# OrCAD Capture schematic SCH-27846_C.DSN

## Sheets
1 TITLE PAGE: title: TWR- KW21D256; rev: C; company: Freescale Semiconductor; note: SCH-27694 PDF: SPF-27694; note: 6501 William Cannon Drive West; note: Austin, TX 78735-8598
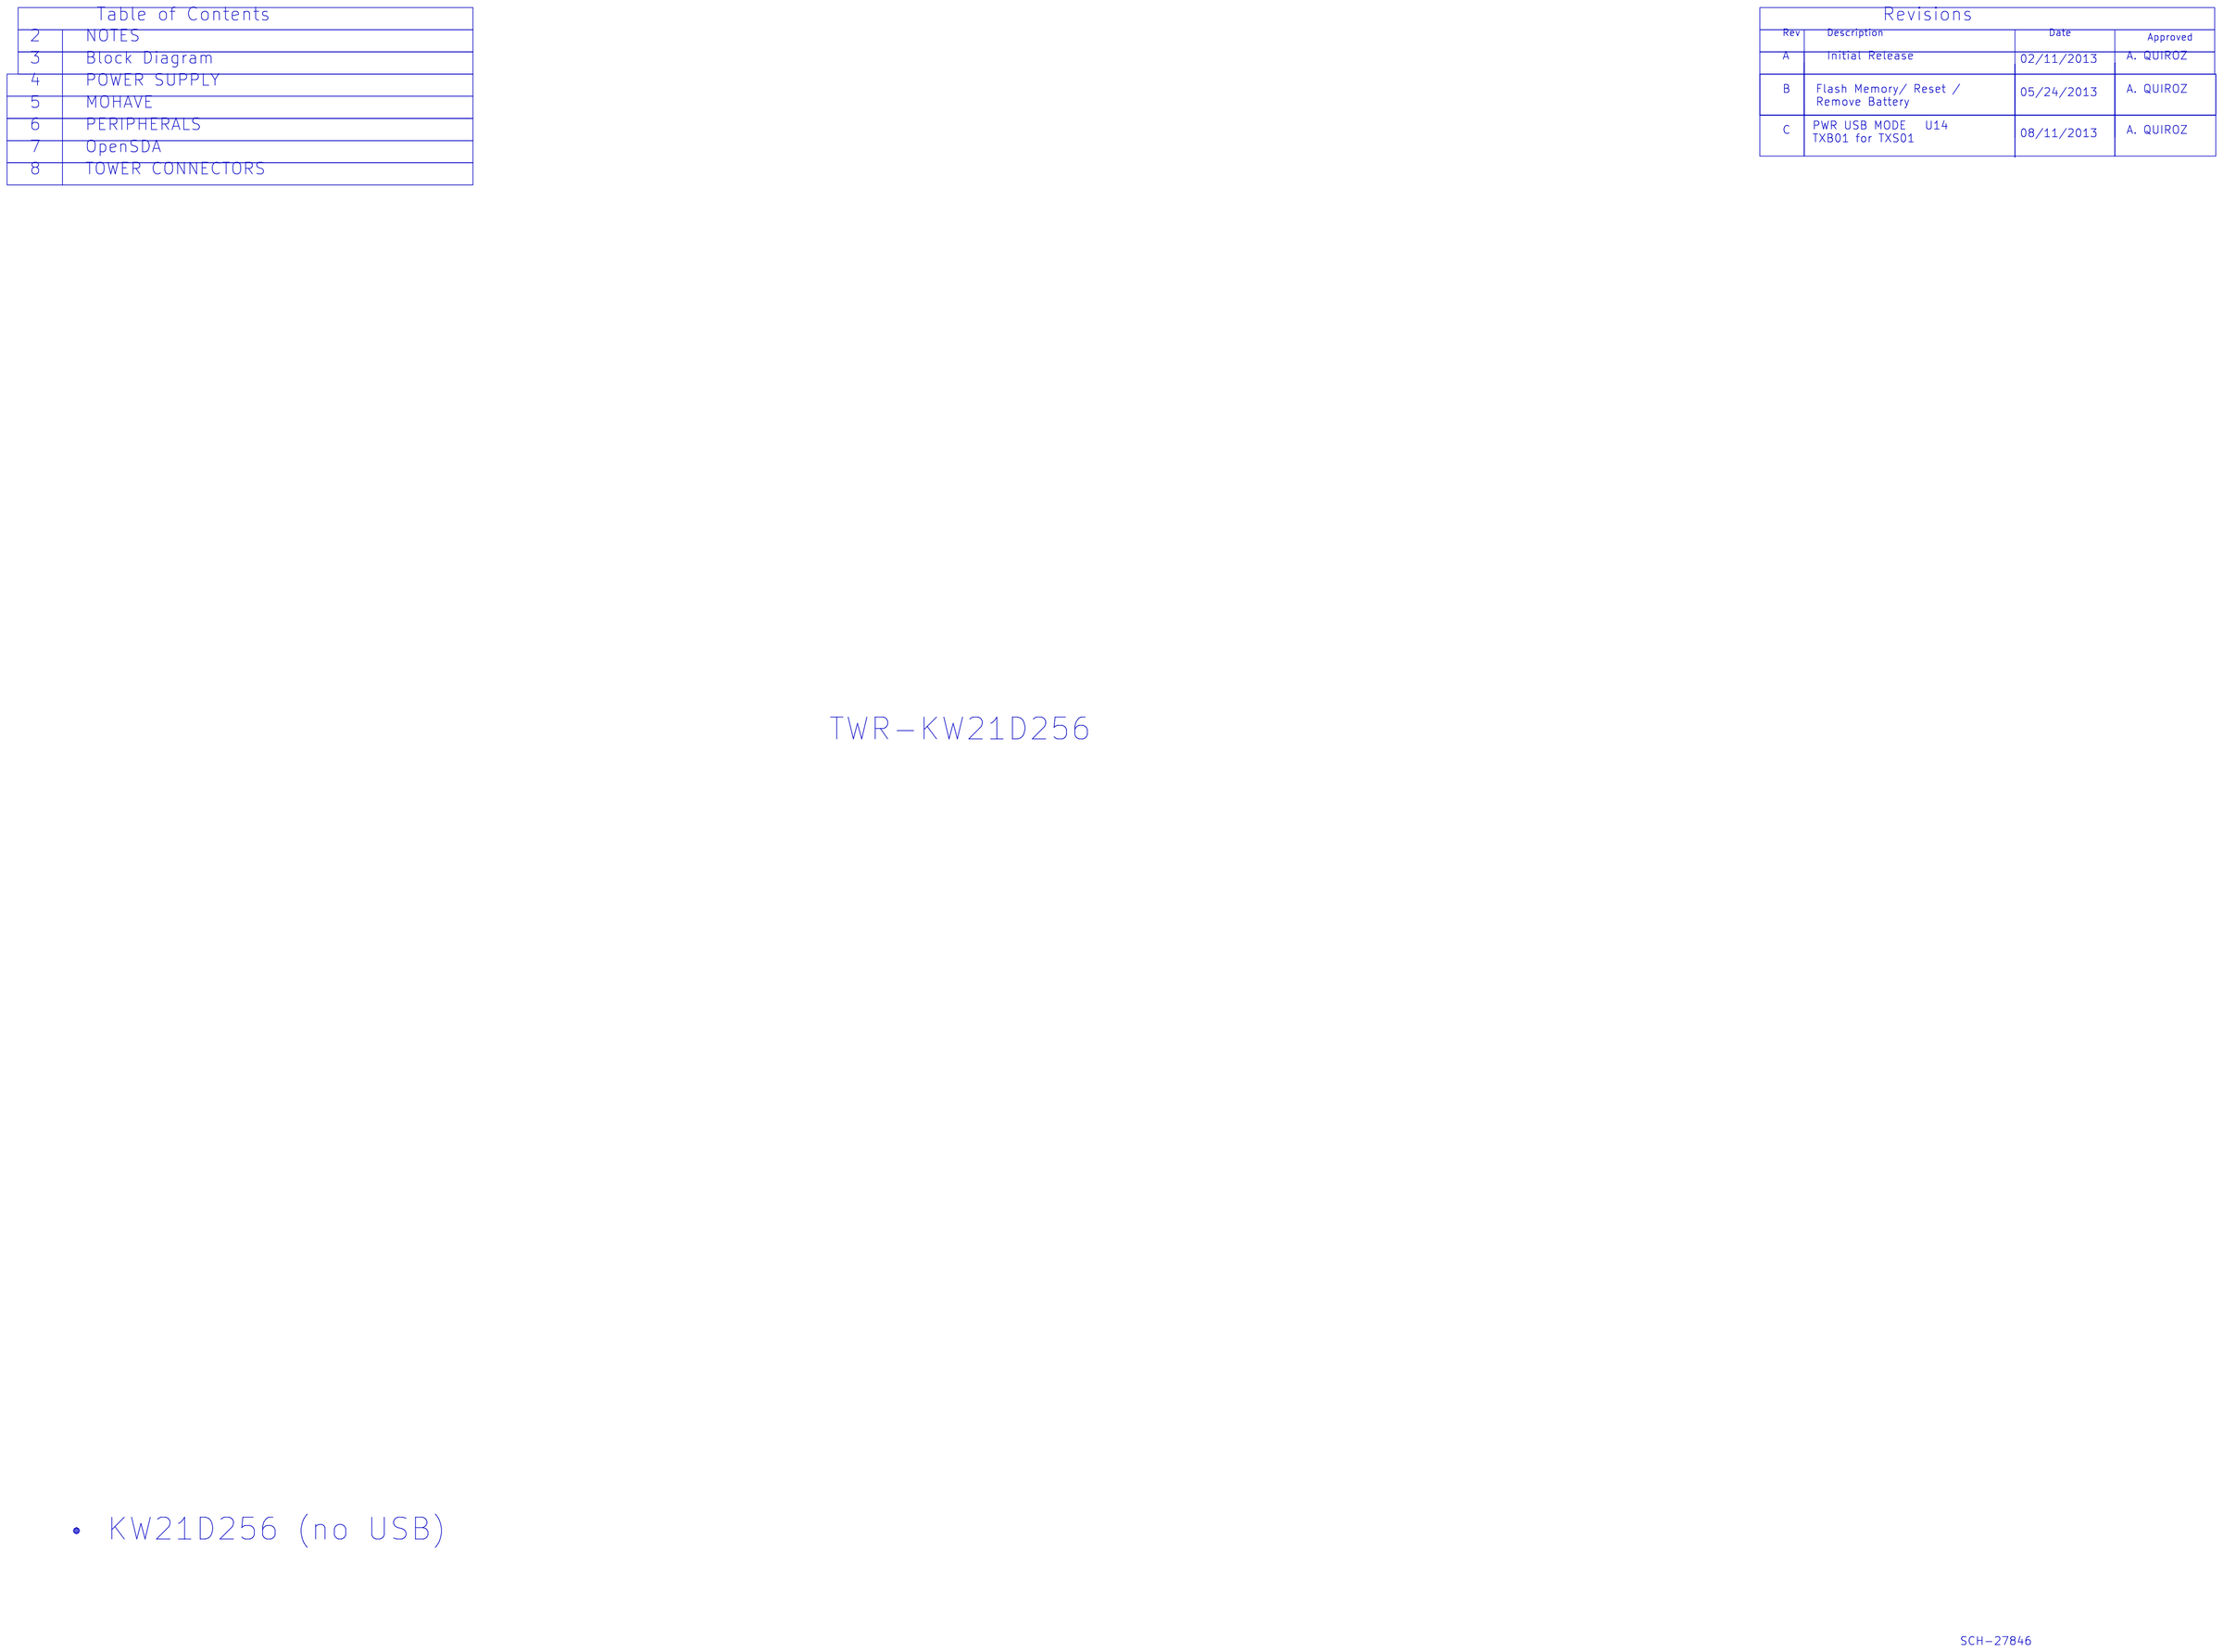
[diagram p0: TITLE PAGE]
2 NOTES: note: SCH-27108 PDF: SPF-27108
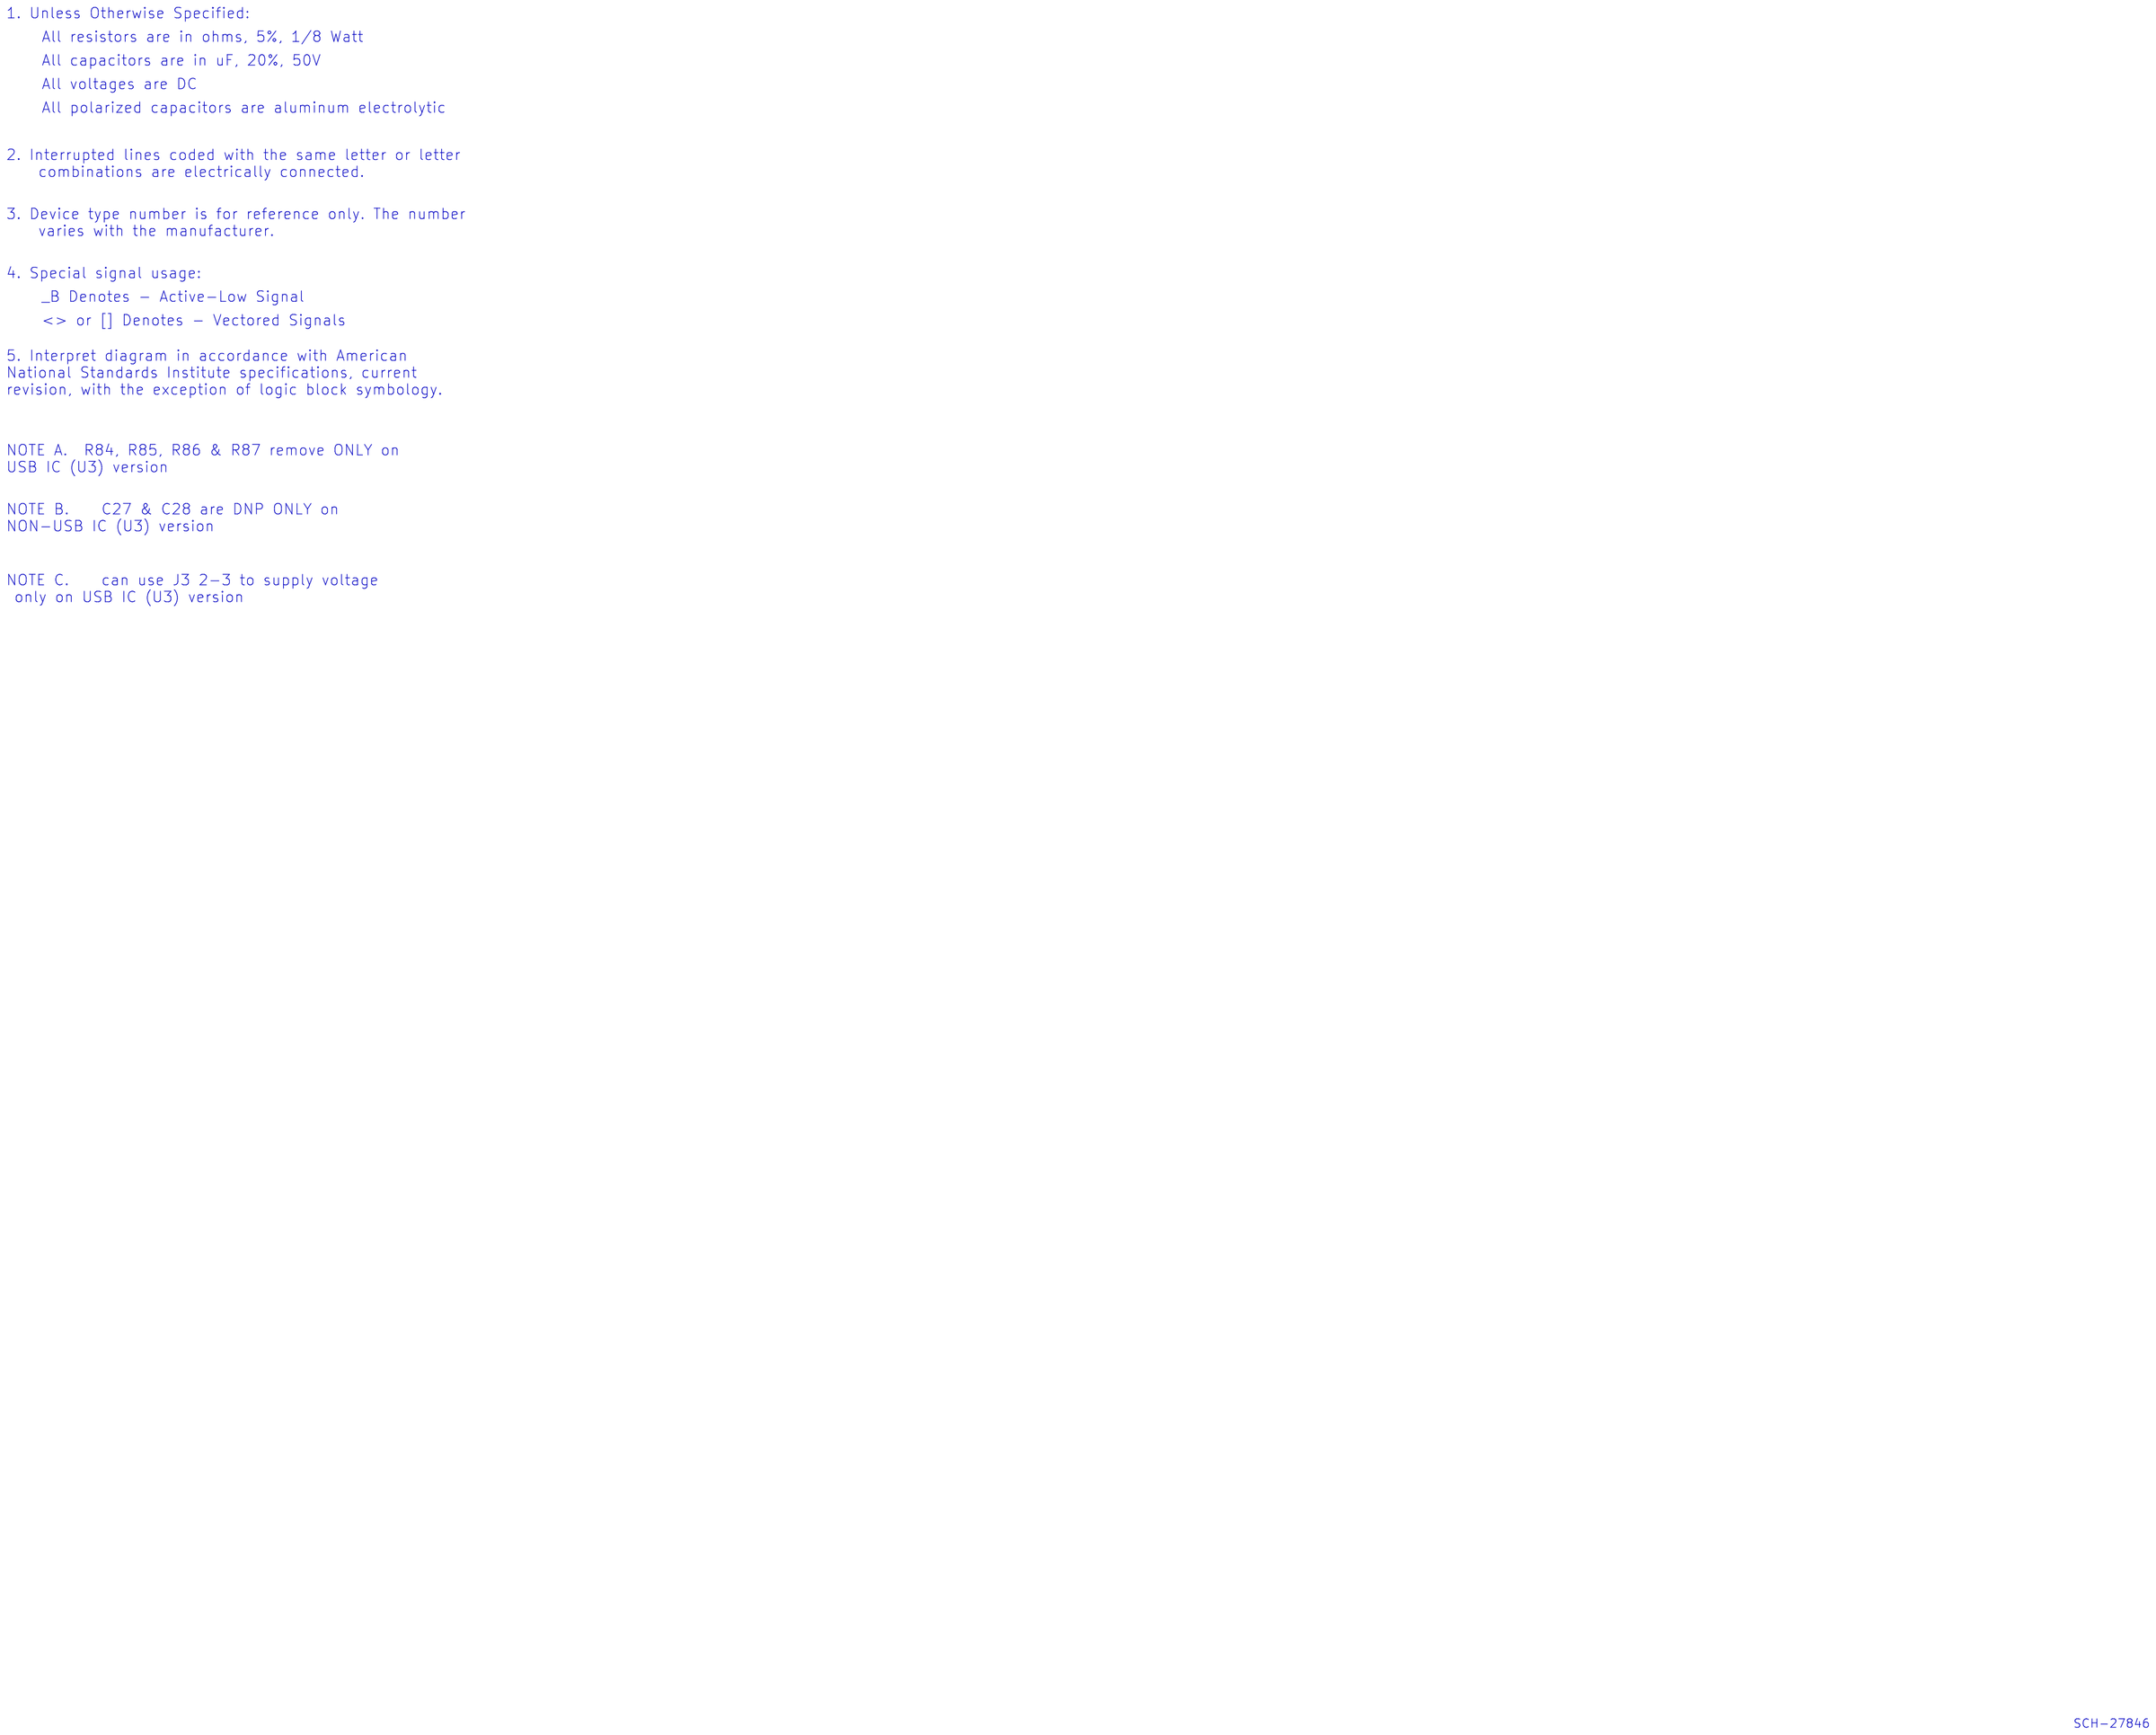
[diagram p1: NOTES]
3 BLOCK DIAGRAM: note: SCH-27108 PDF: SPF-27108
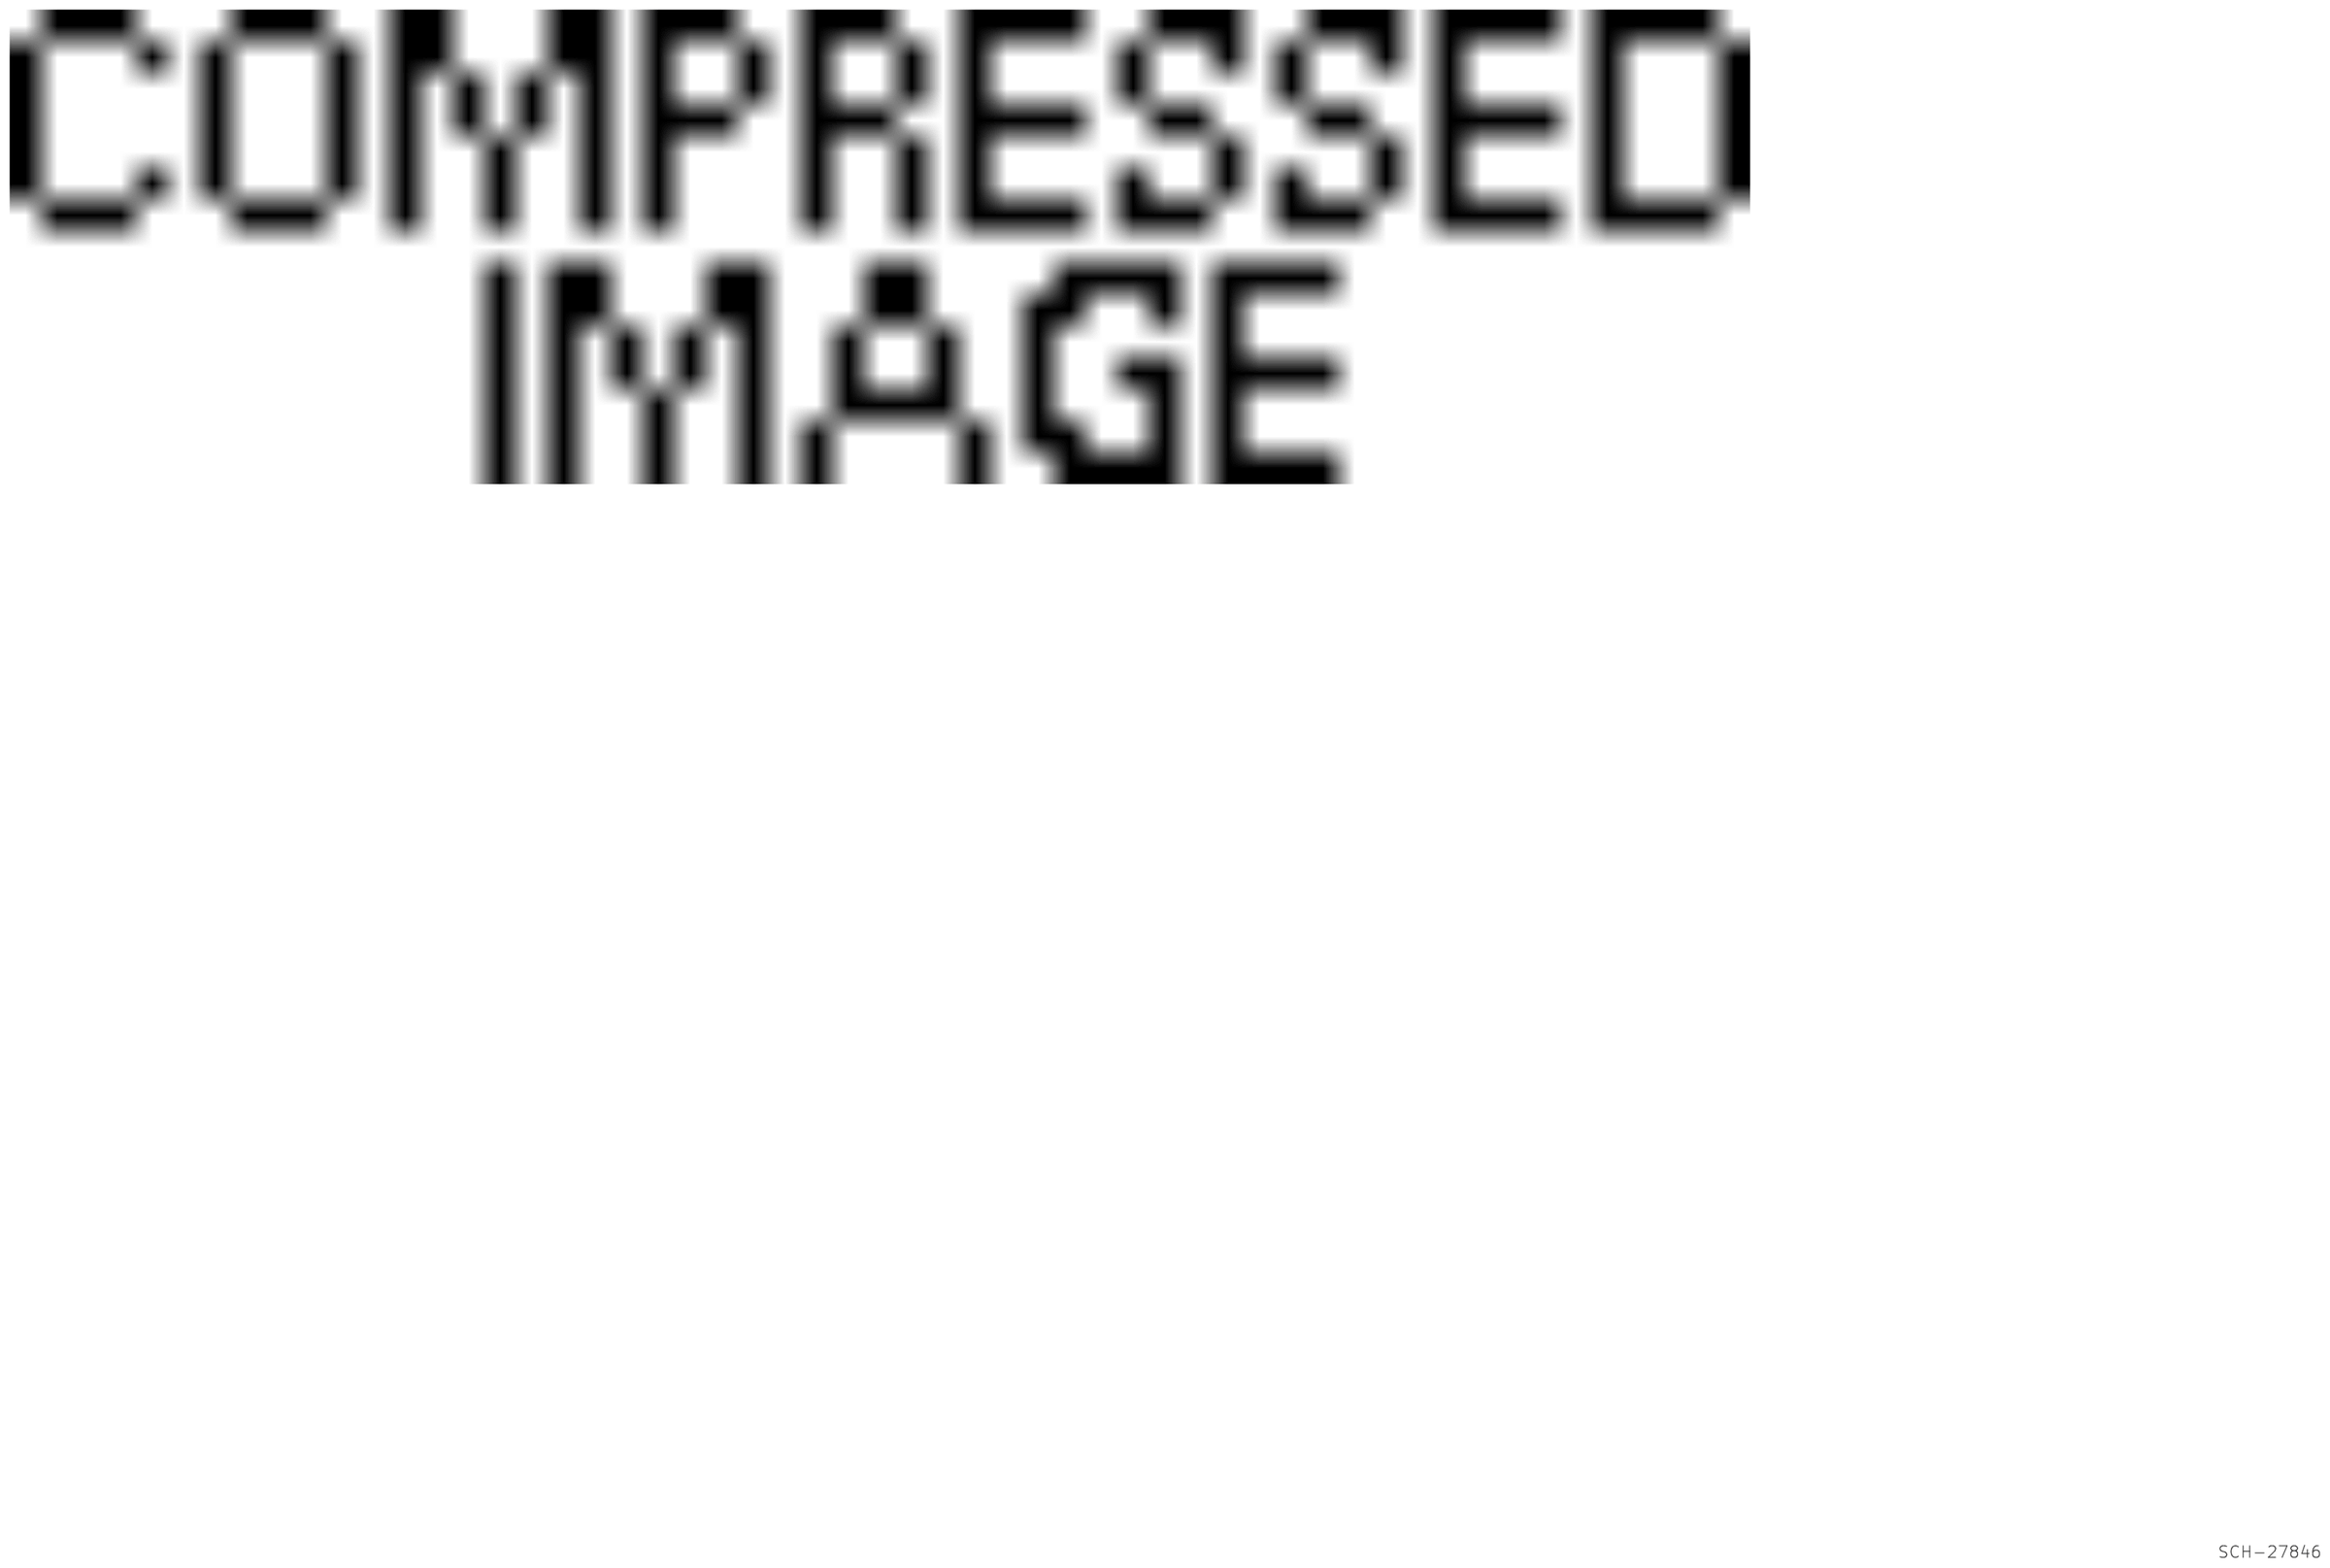
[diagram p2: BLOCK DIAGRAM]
4 POWER SUPPLY: size C; note: SCH-27108 PDF: SPF-27108
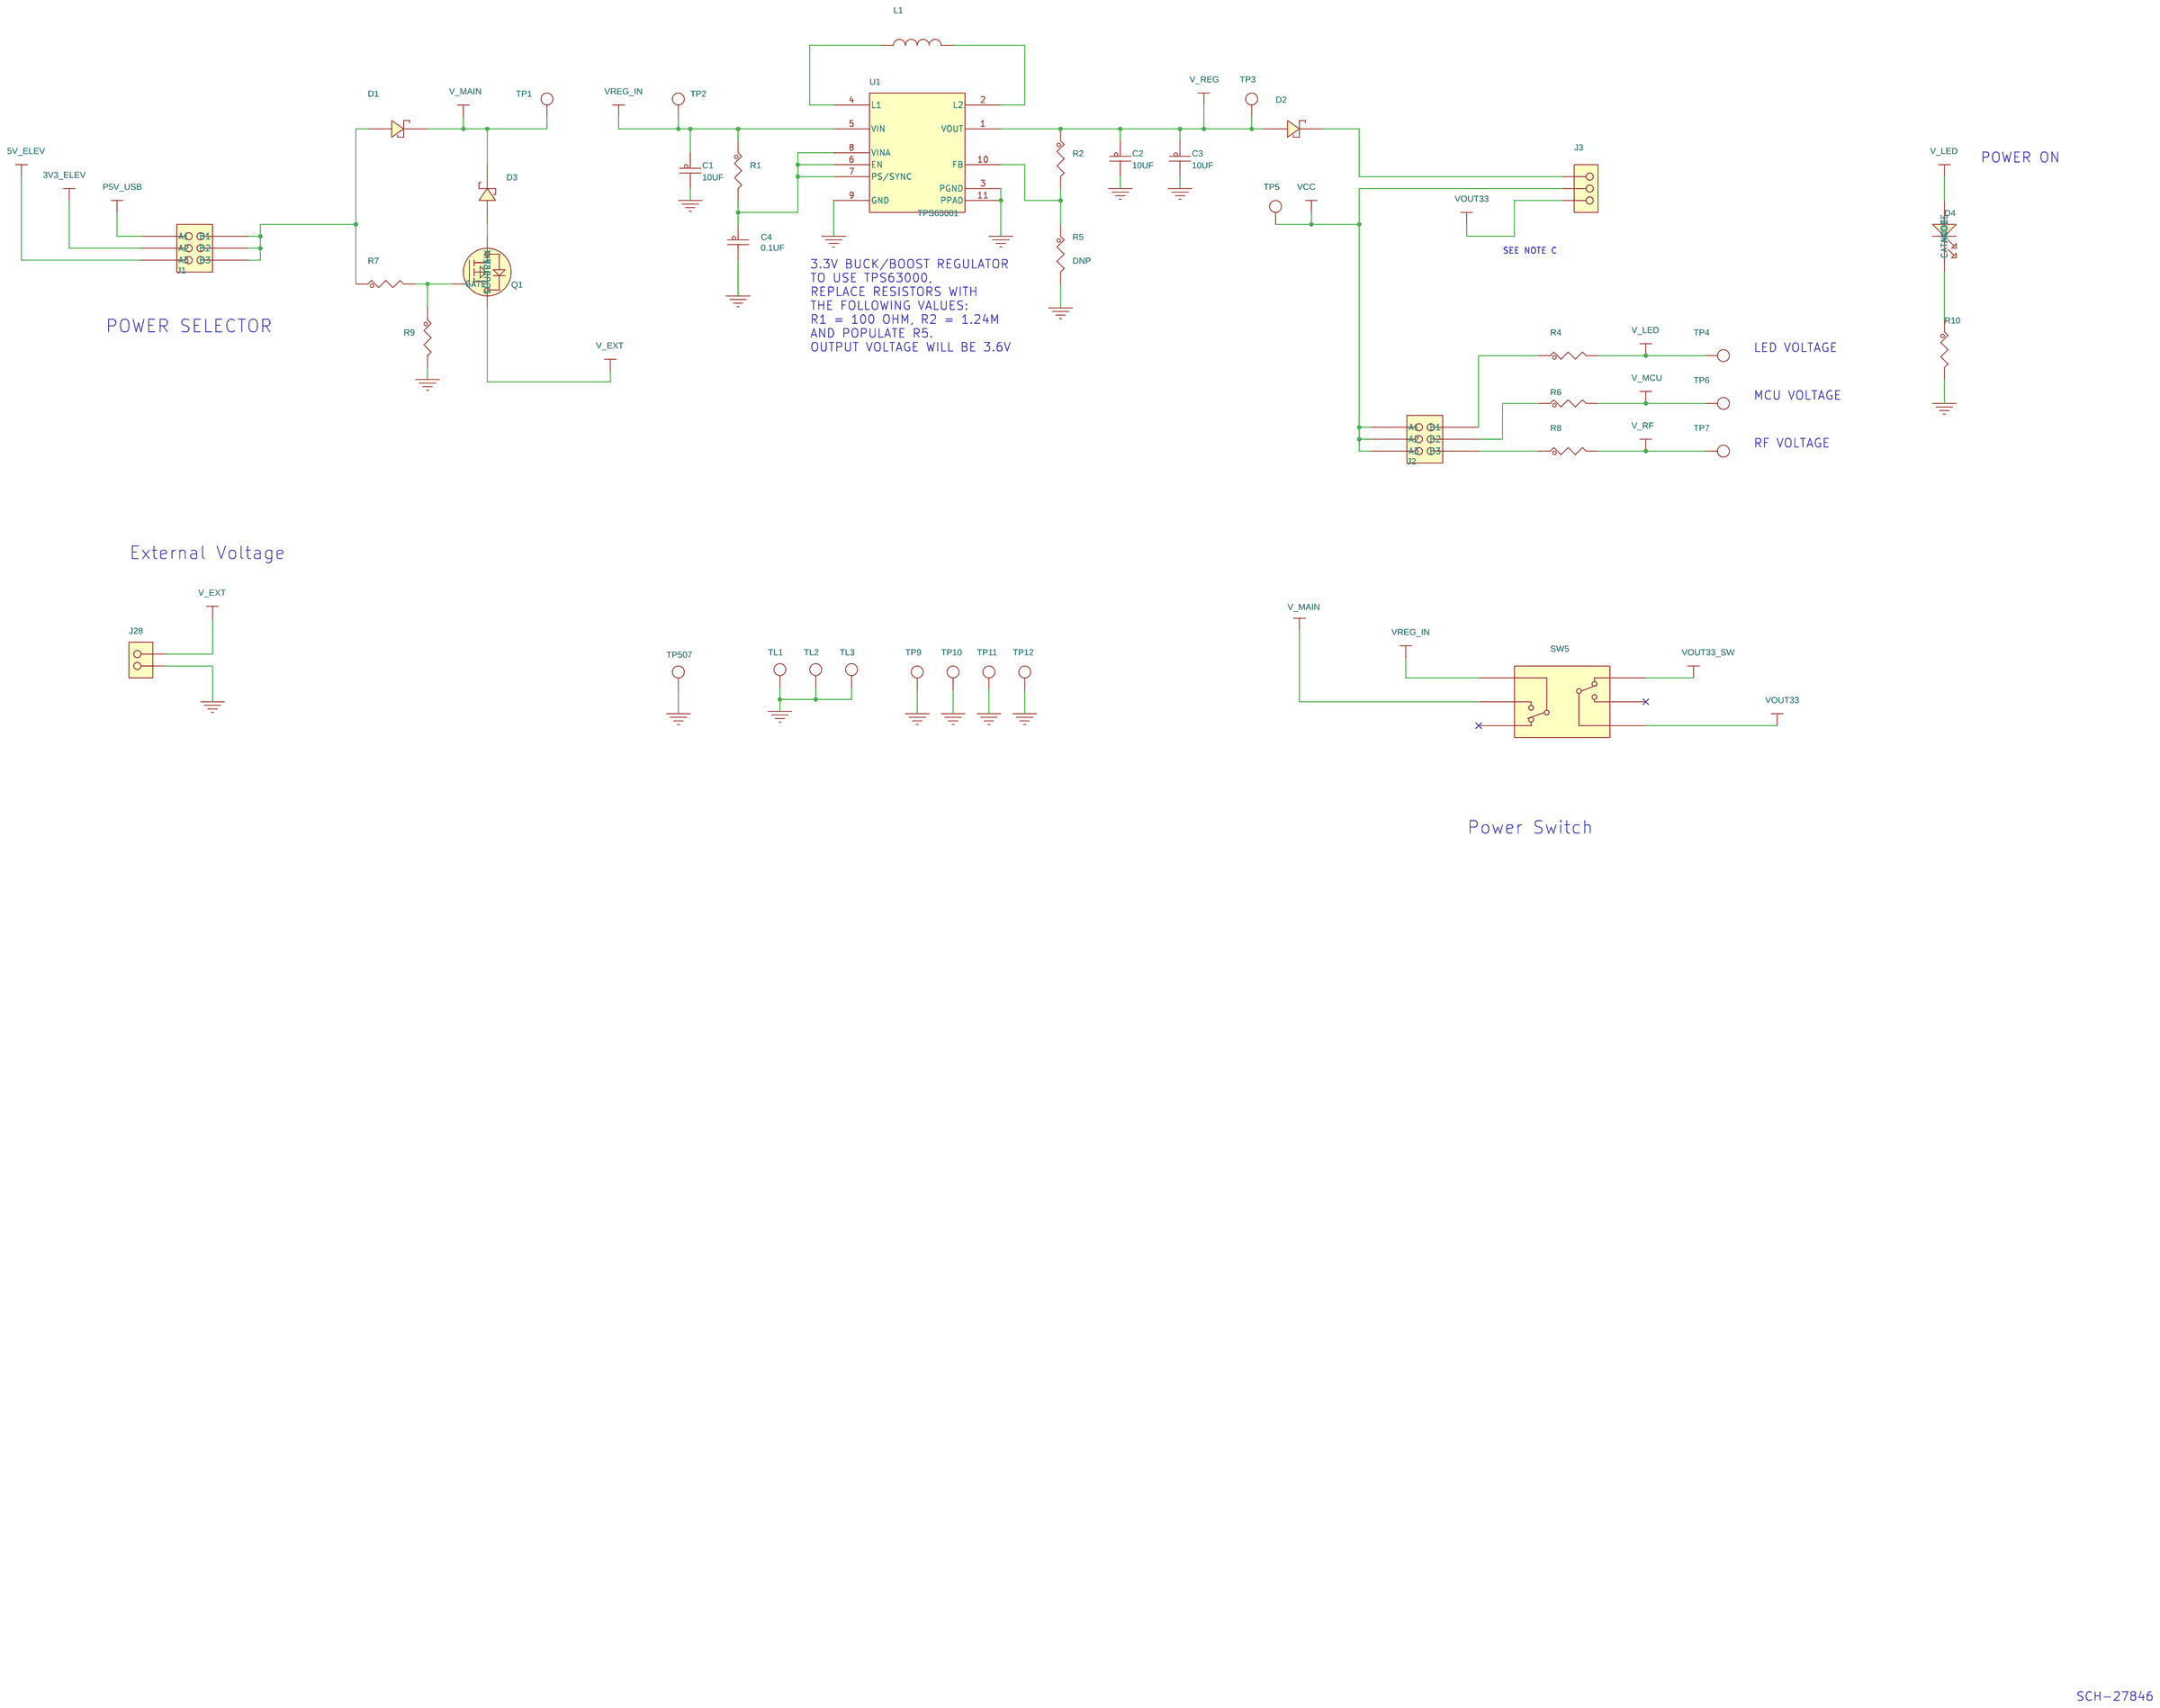
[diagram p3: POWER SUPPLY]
5 MOHAVE: size C; note: SCH-XXXXX PDF: SPF-XXXXX
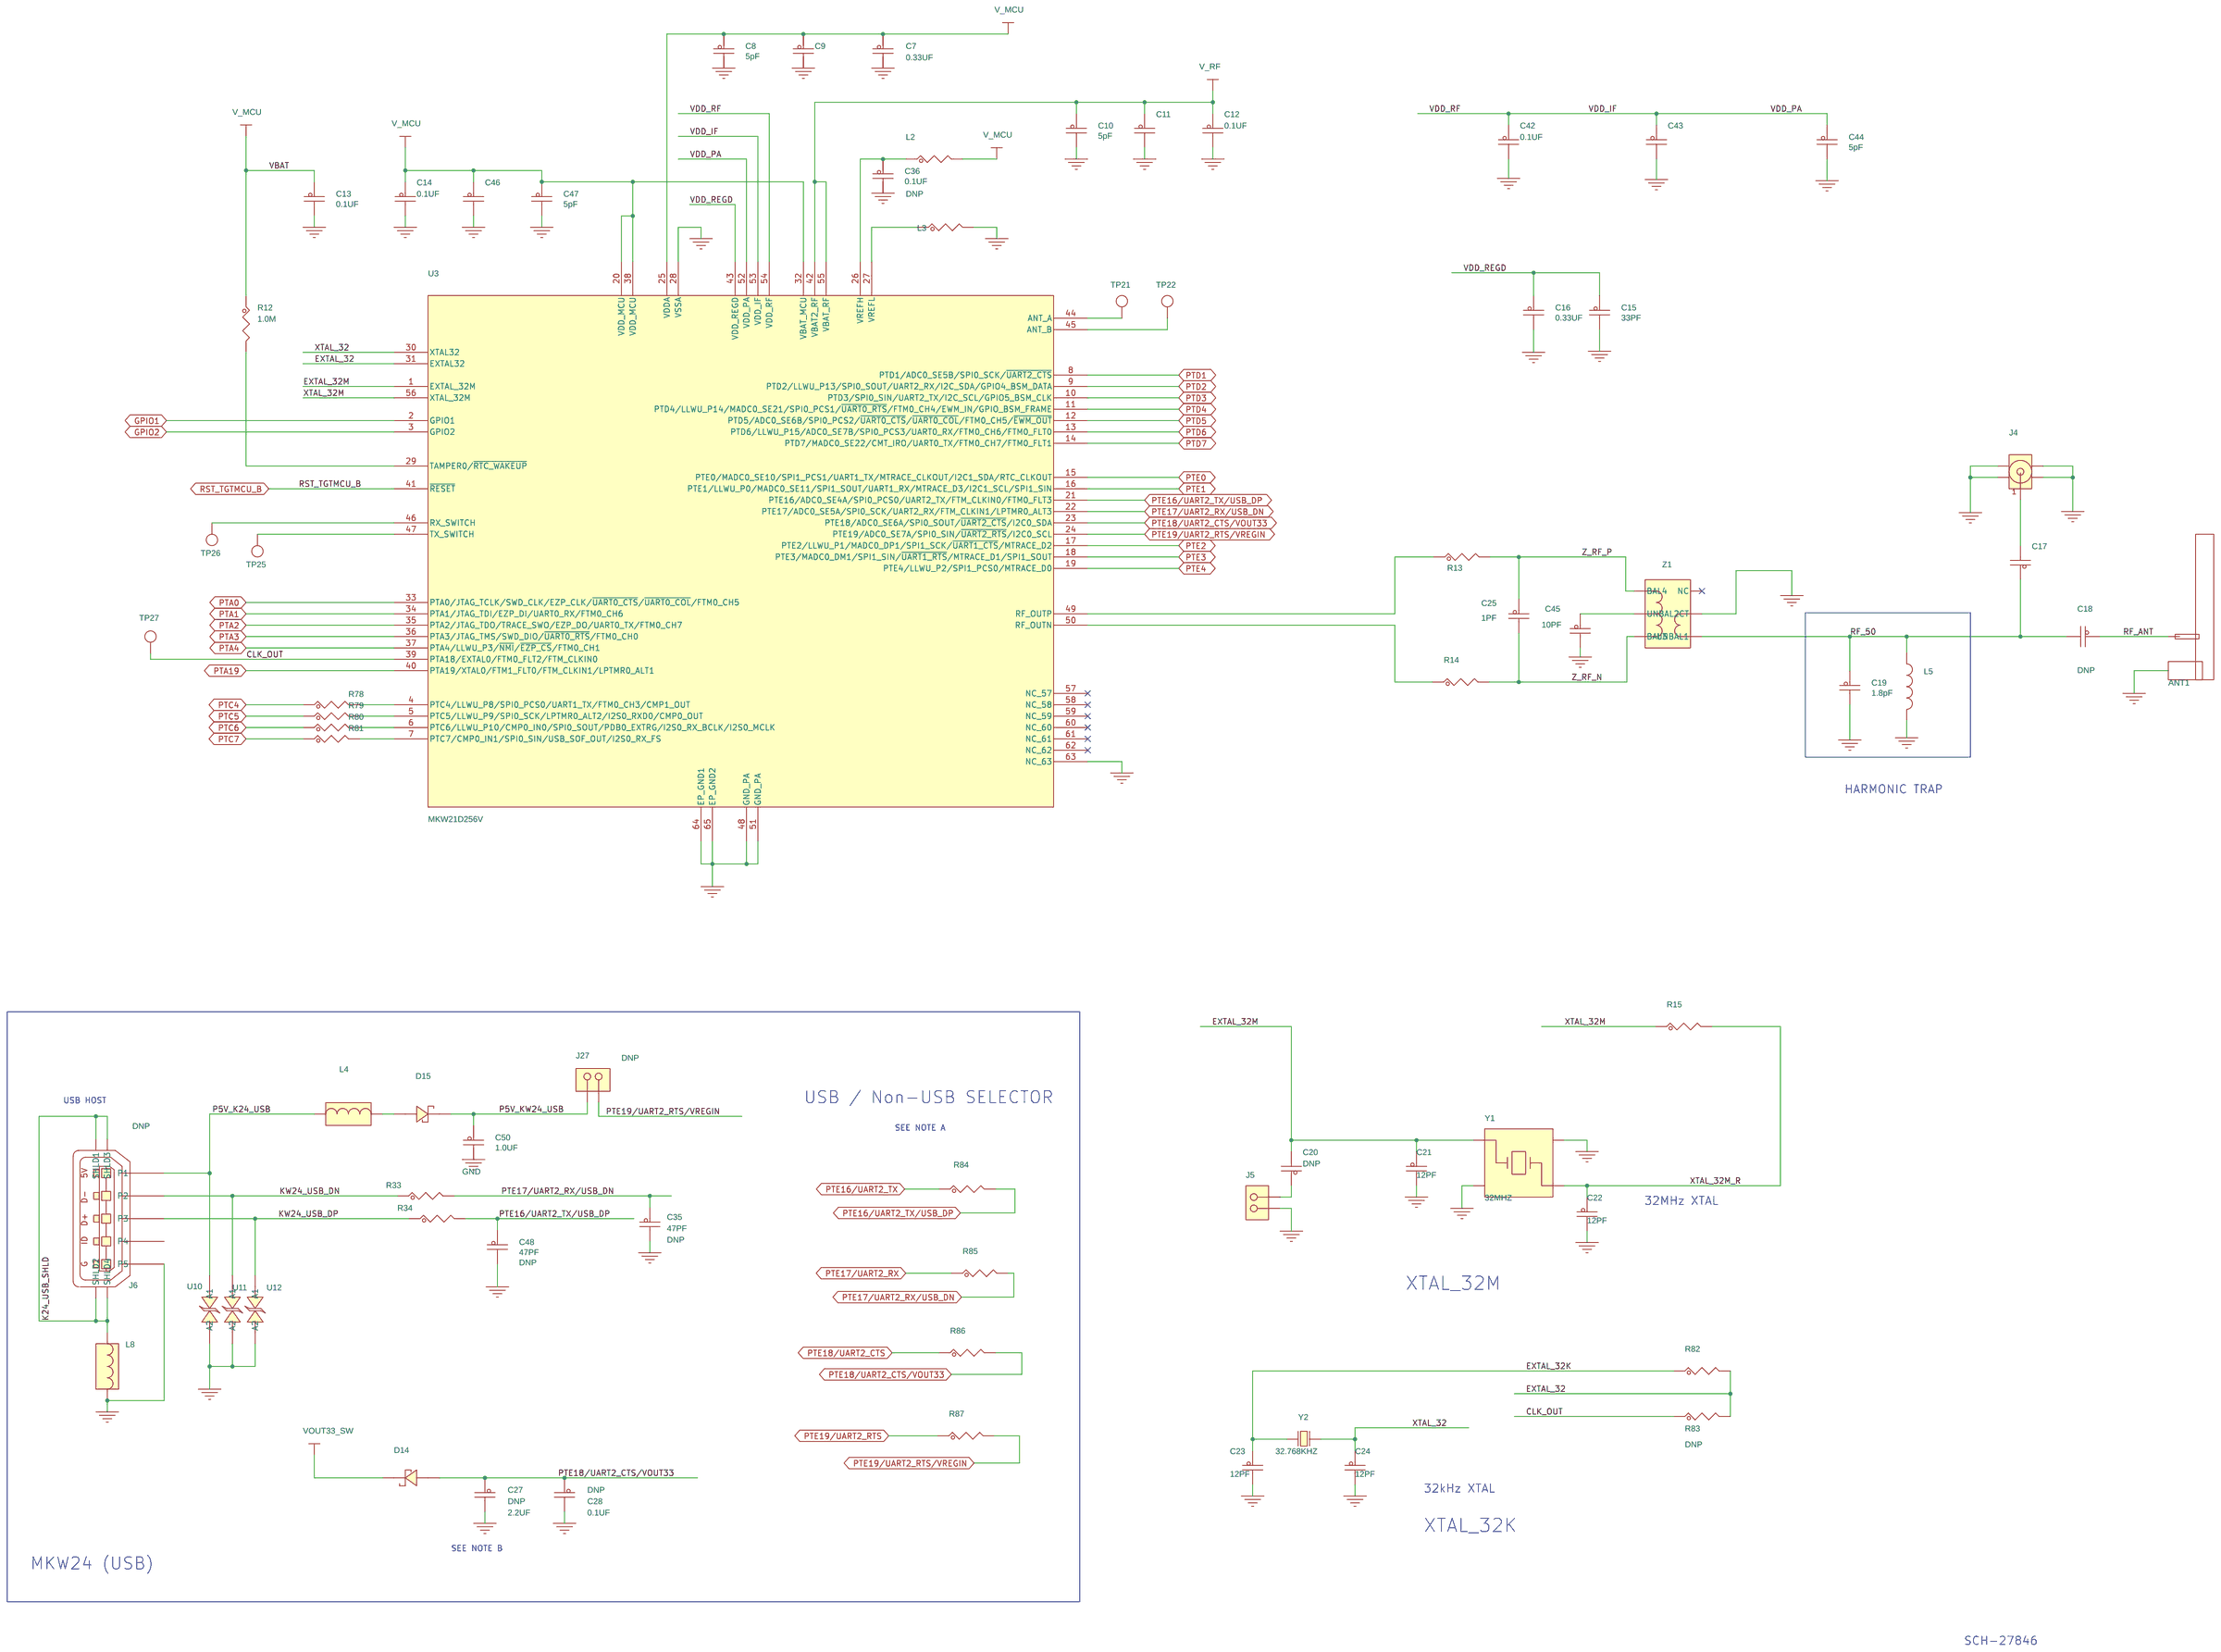
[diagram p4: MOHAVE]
6 06 PERIPHERALS: size C; note: SCH-XXXXX PDF: SPF-XXXXX
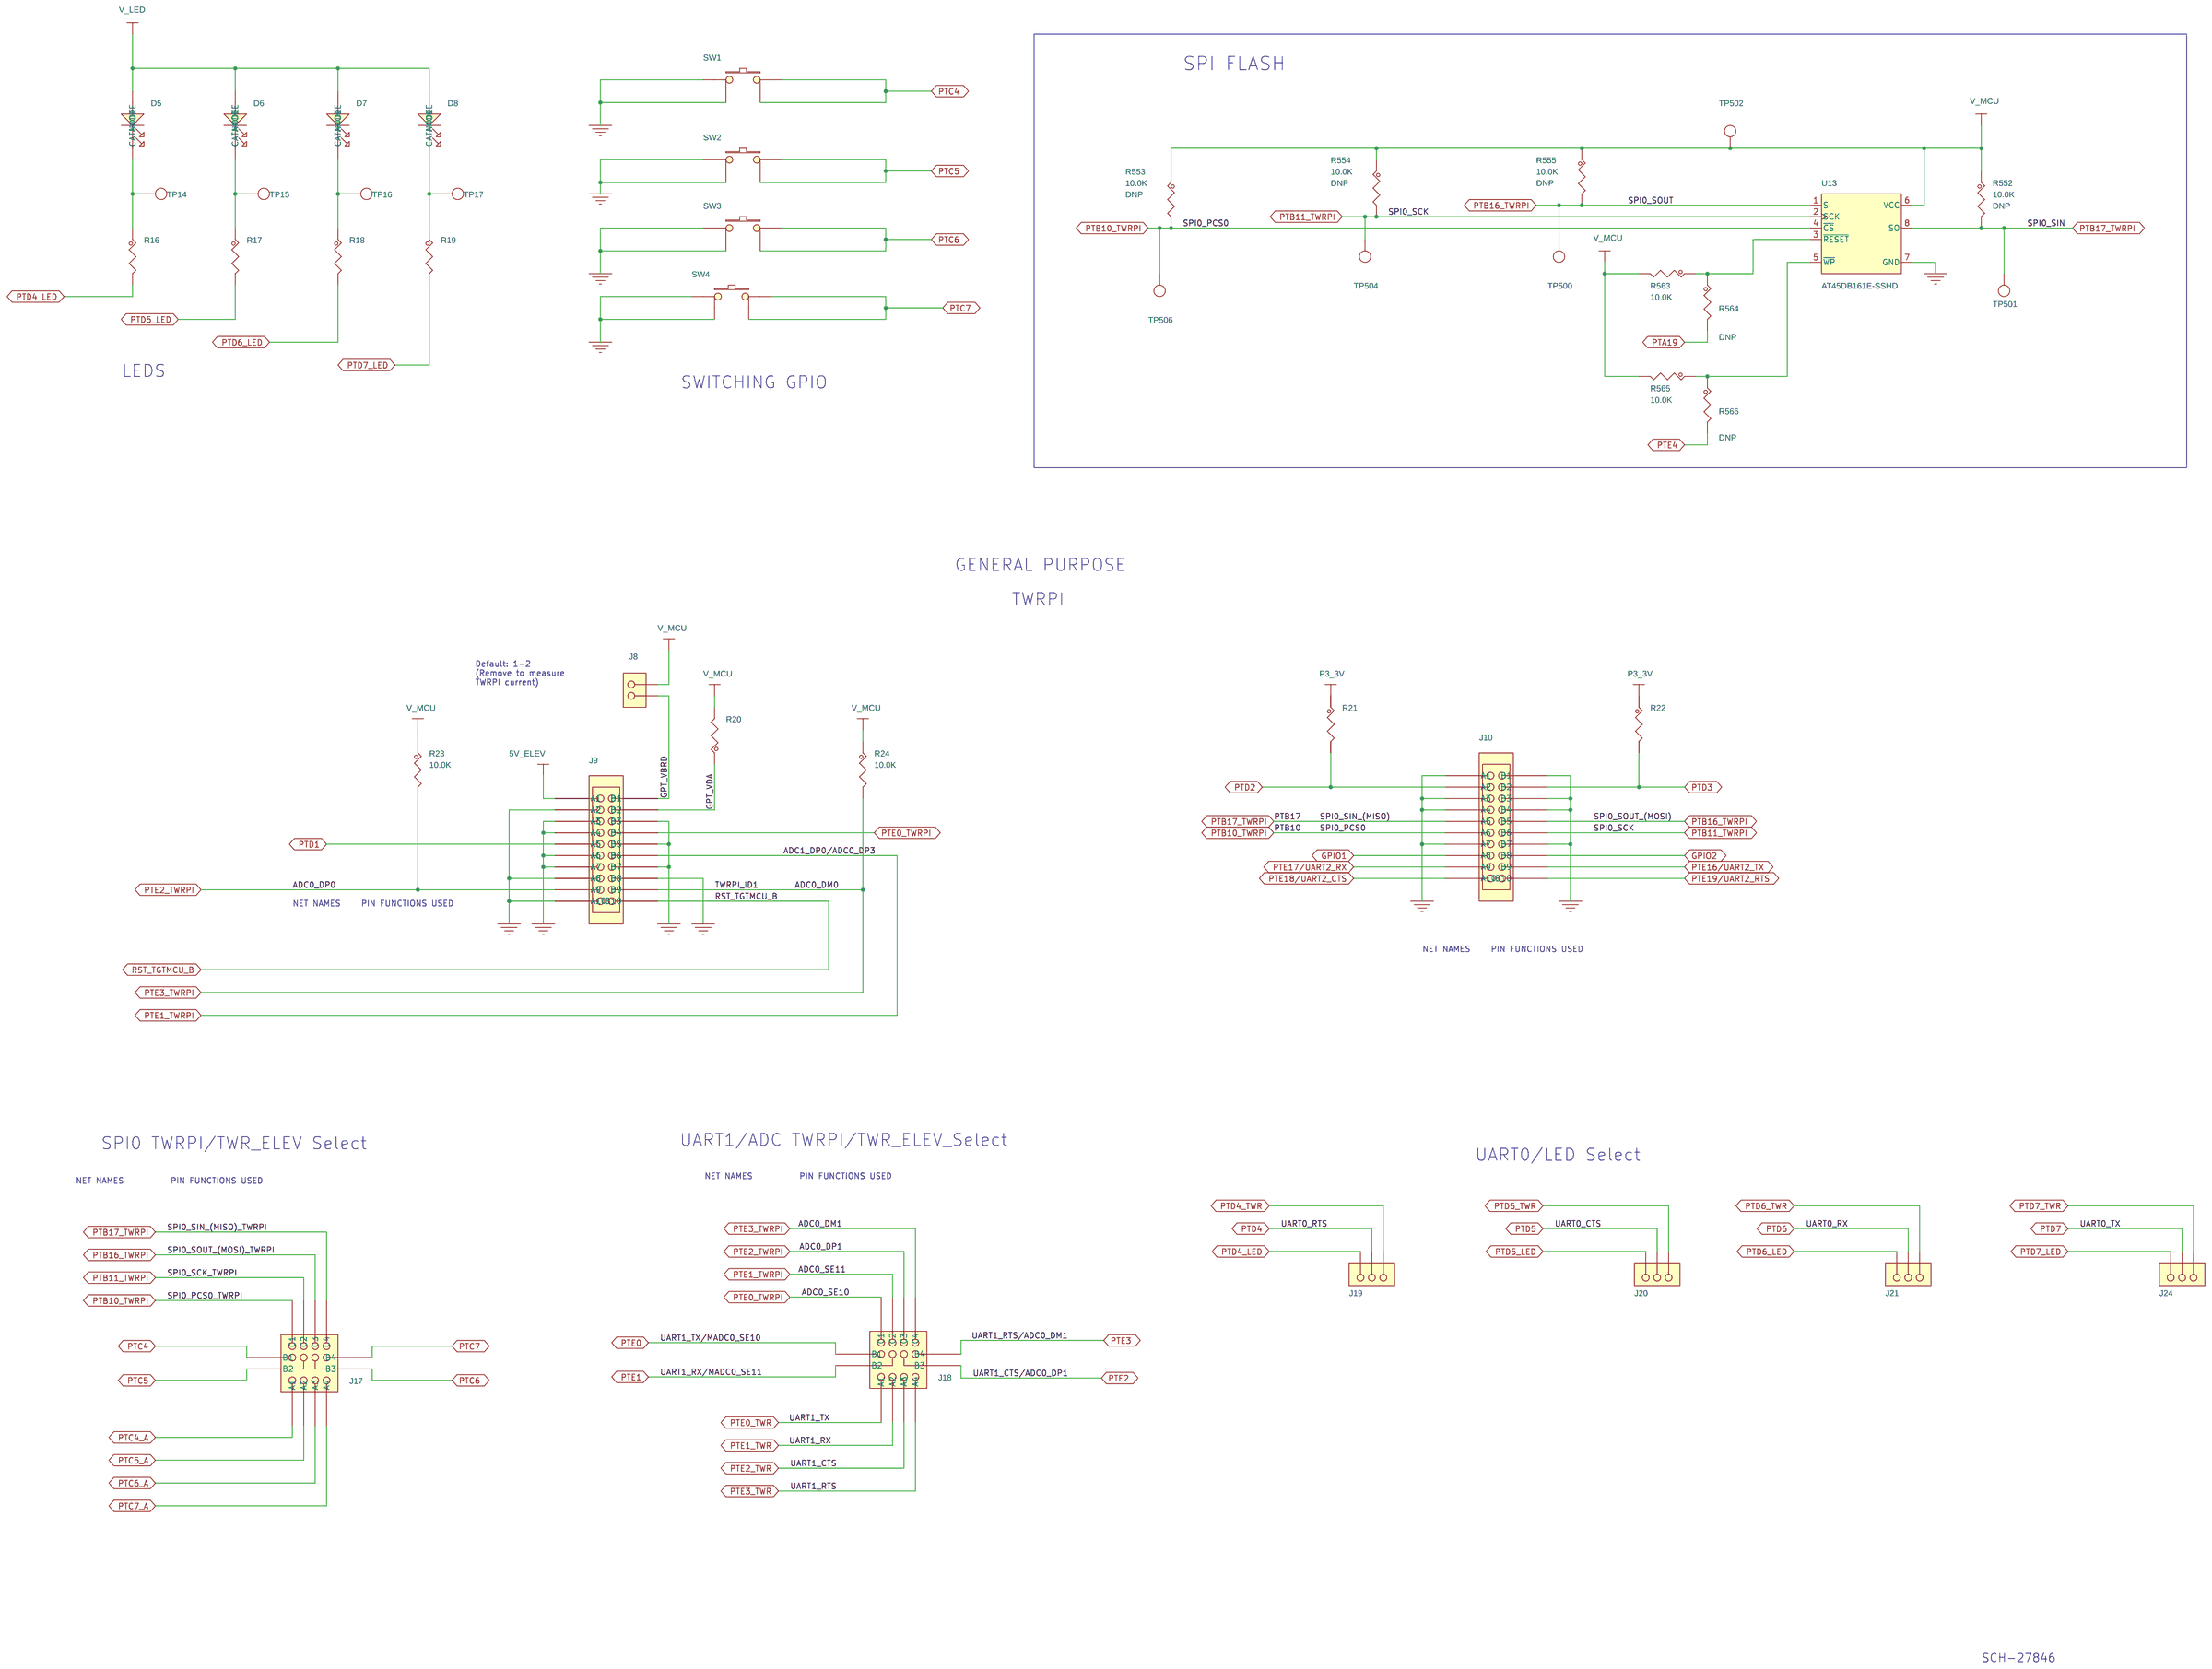
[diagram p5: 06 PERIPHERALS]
7 07 OpenSDA: size C; note: SCH-XXXXX PDF: SPF-XXXXX
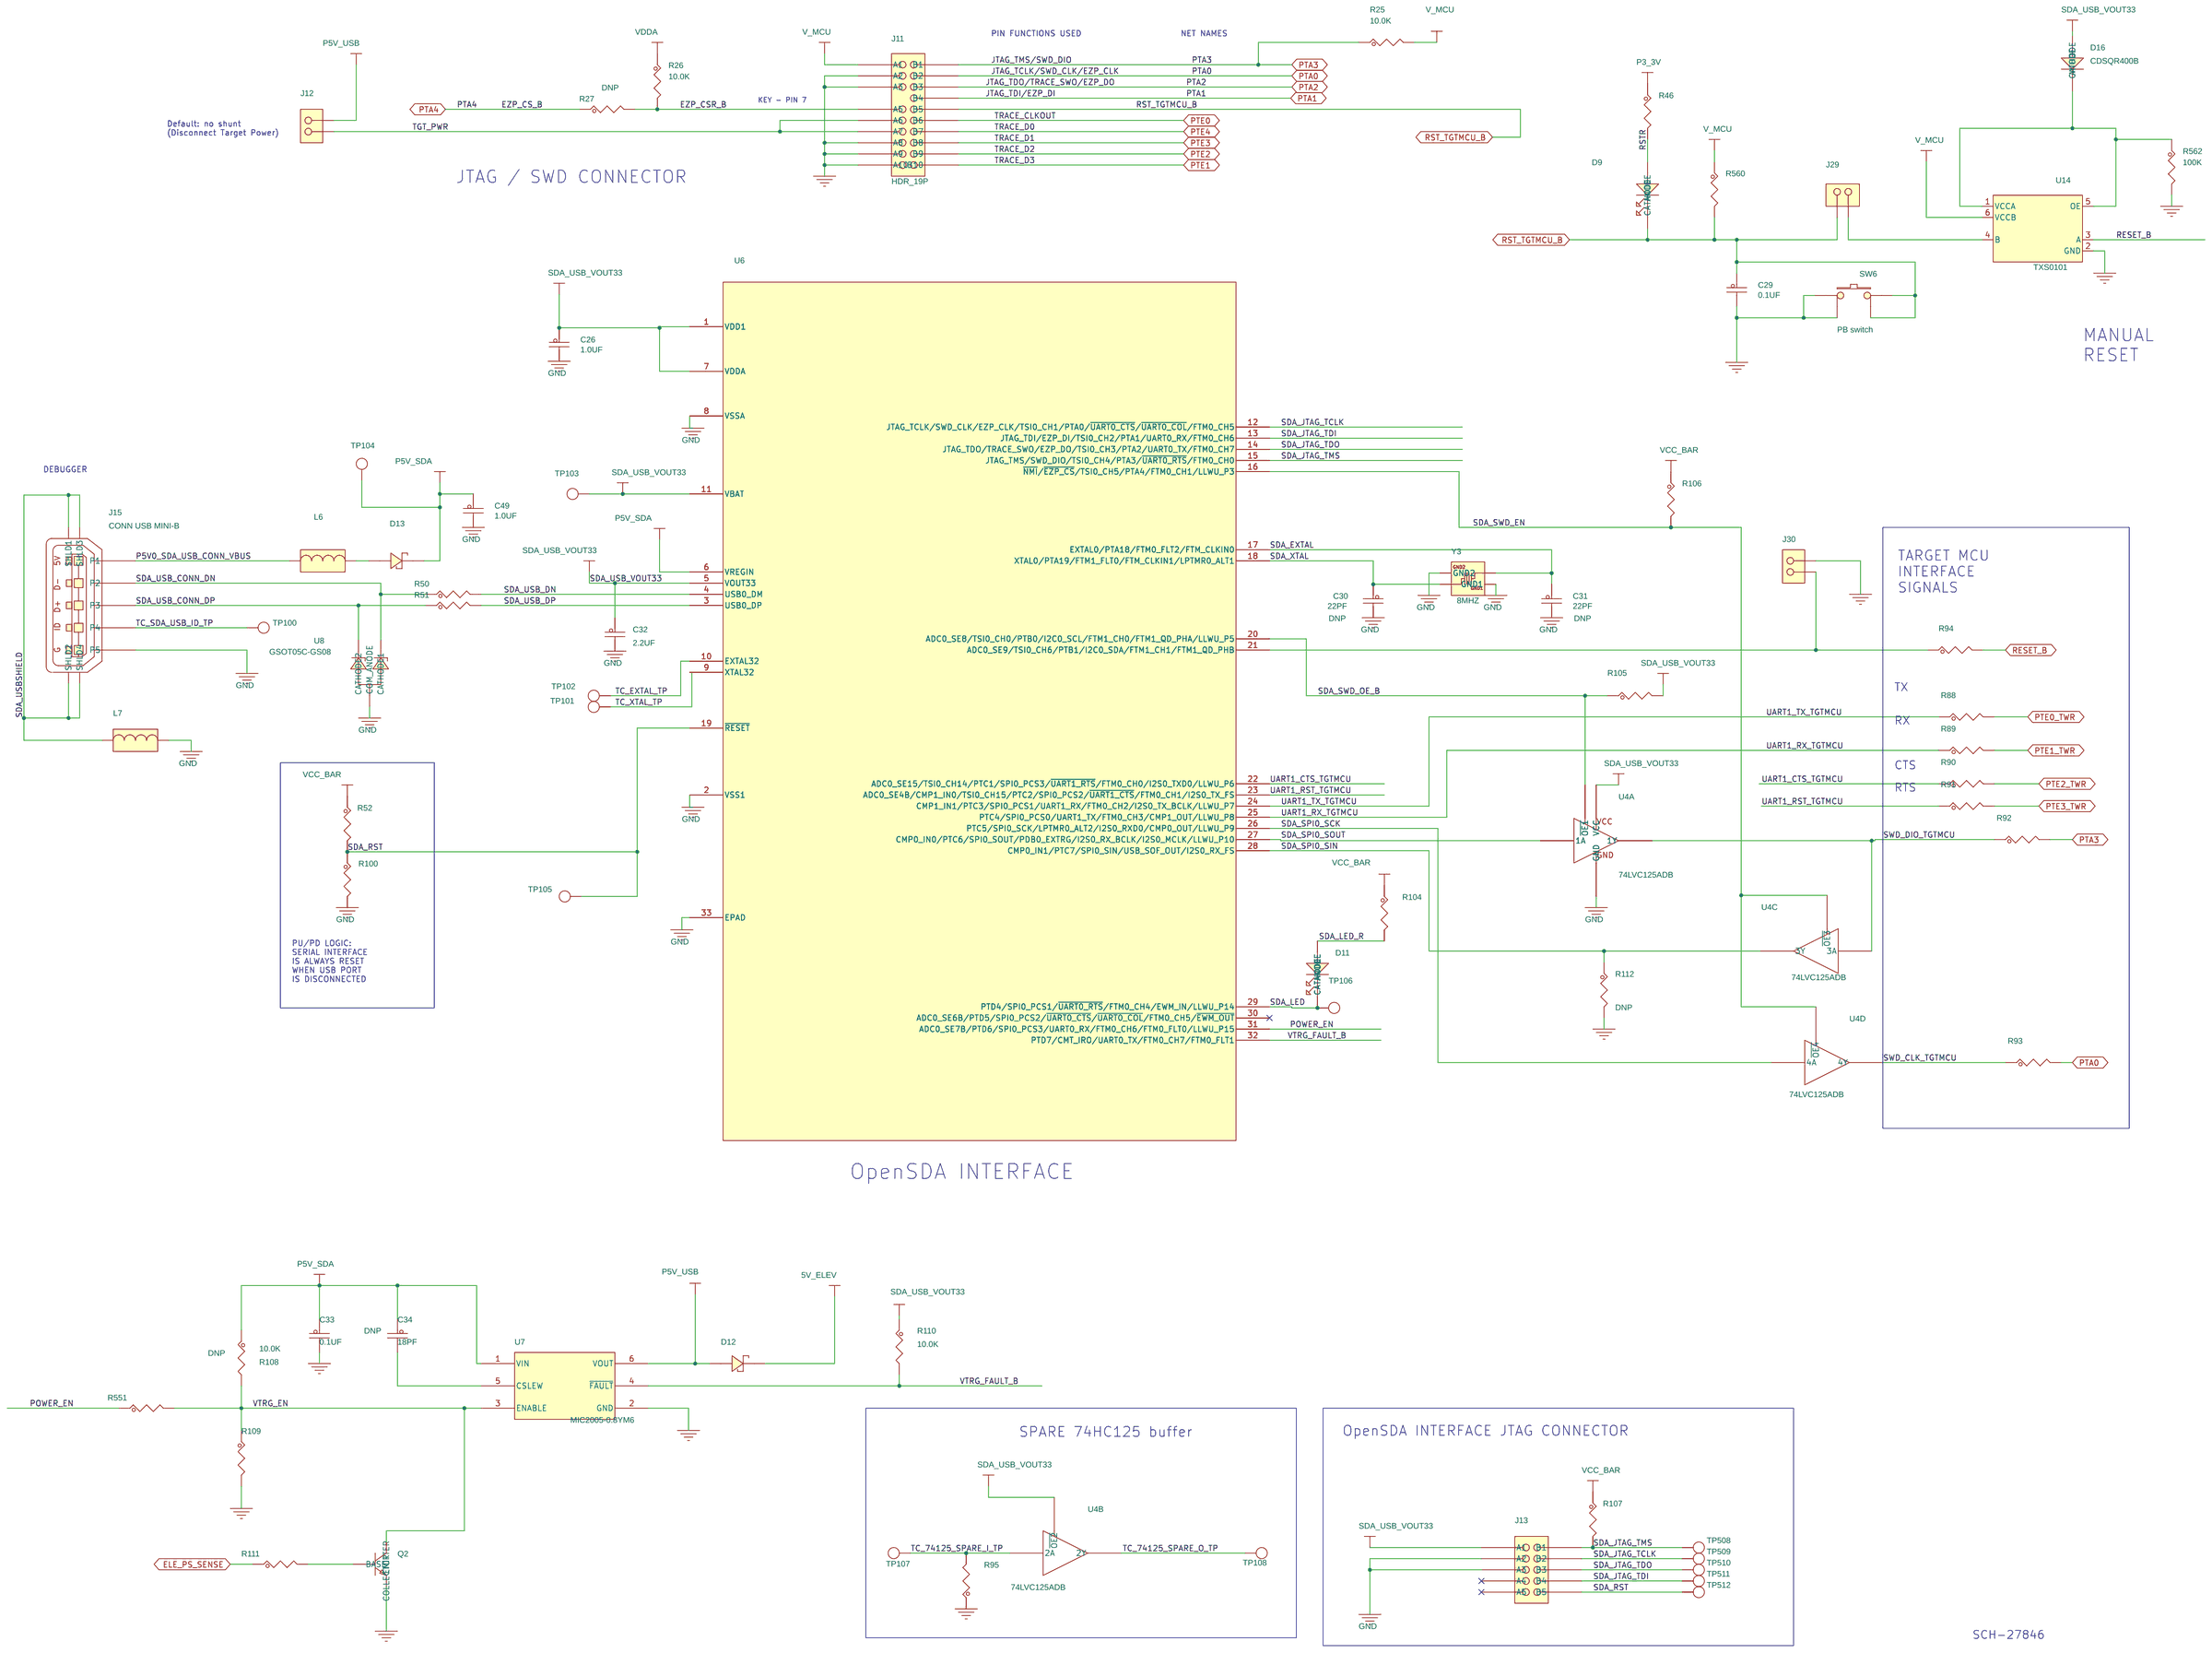
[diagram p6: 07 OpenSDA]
8 08 TOWER CONNECTORS: size C; note: 27694SCH-27694 PDF: SPF-
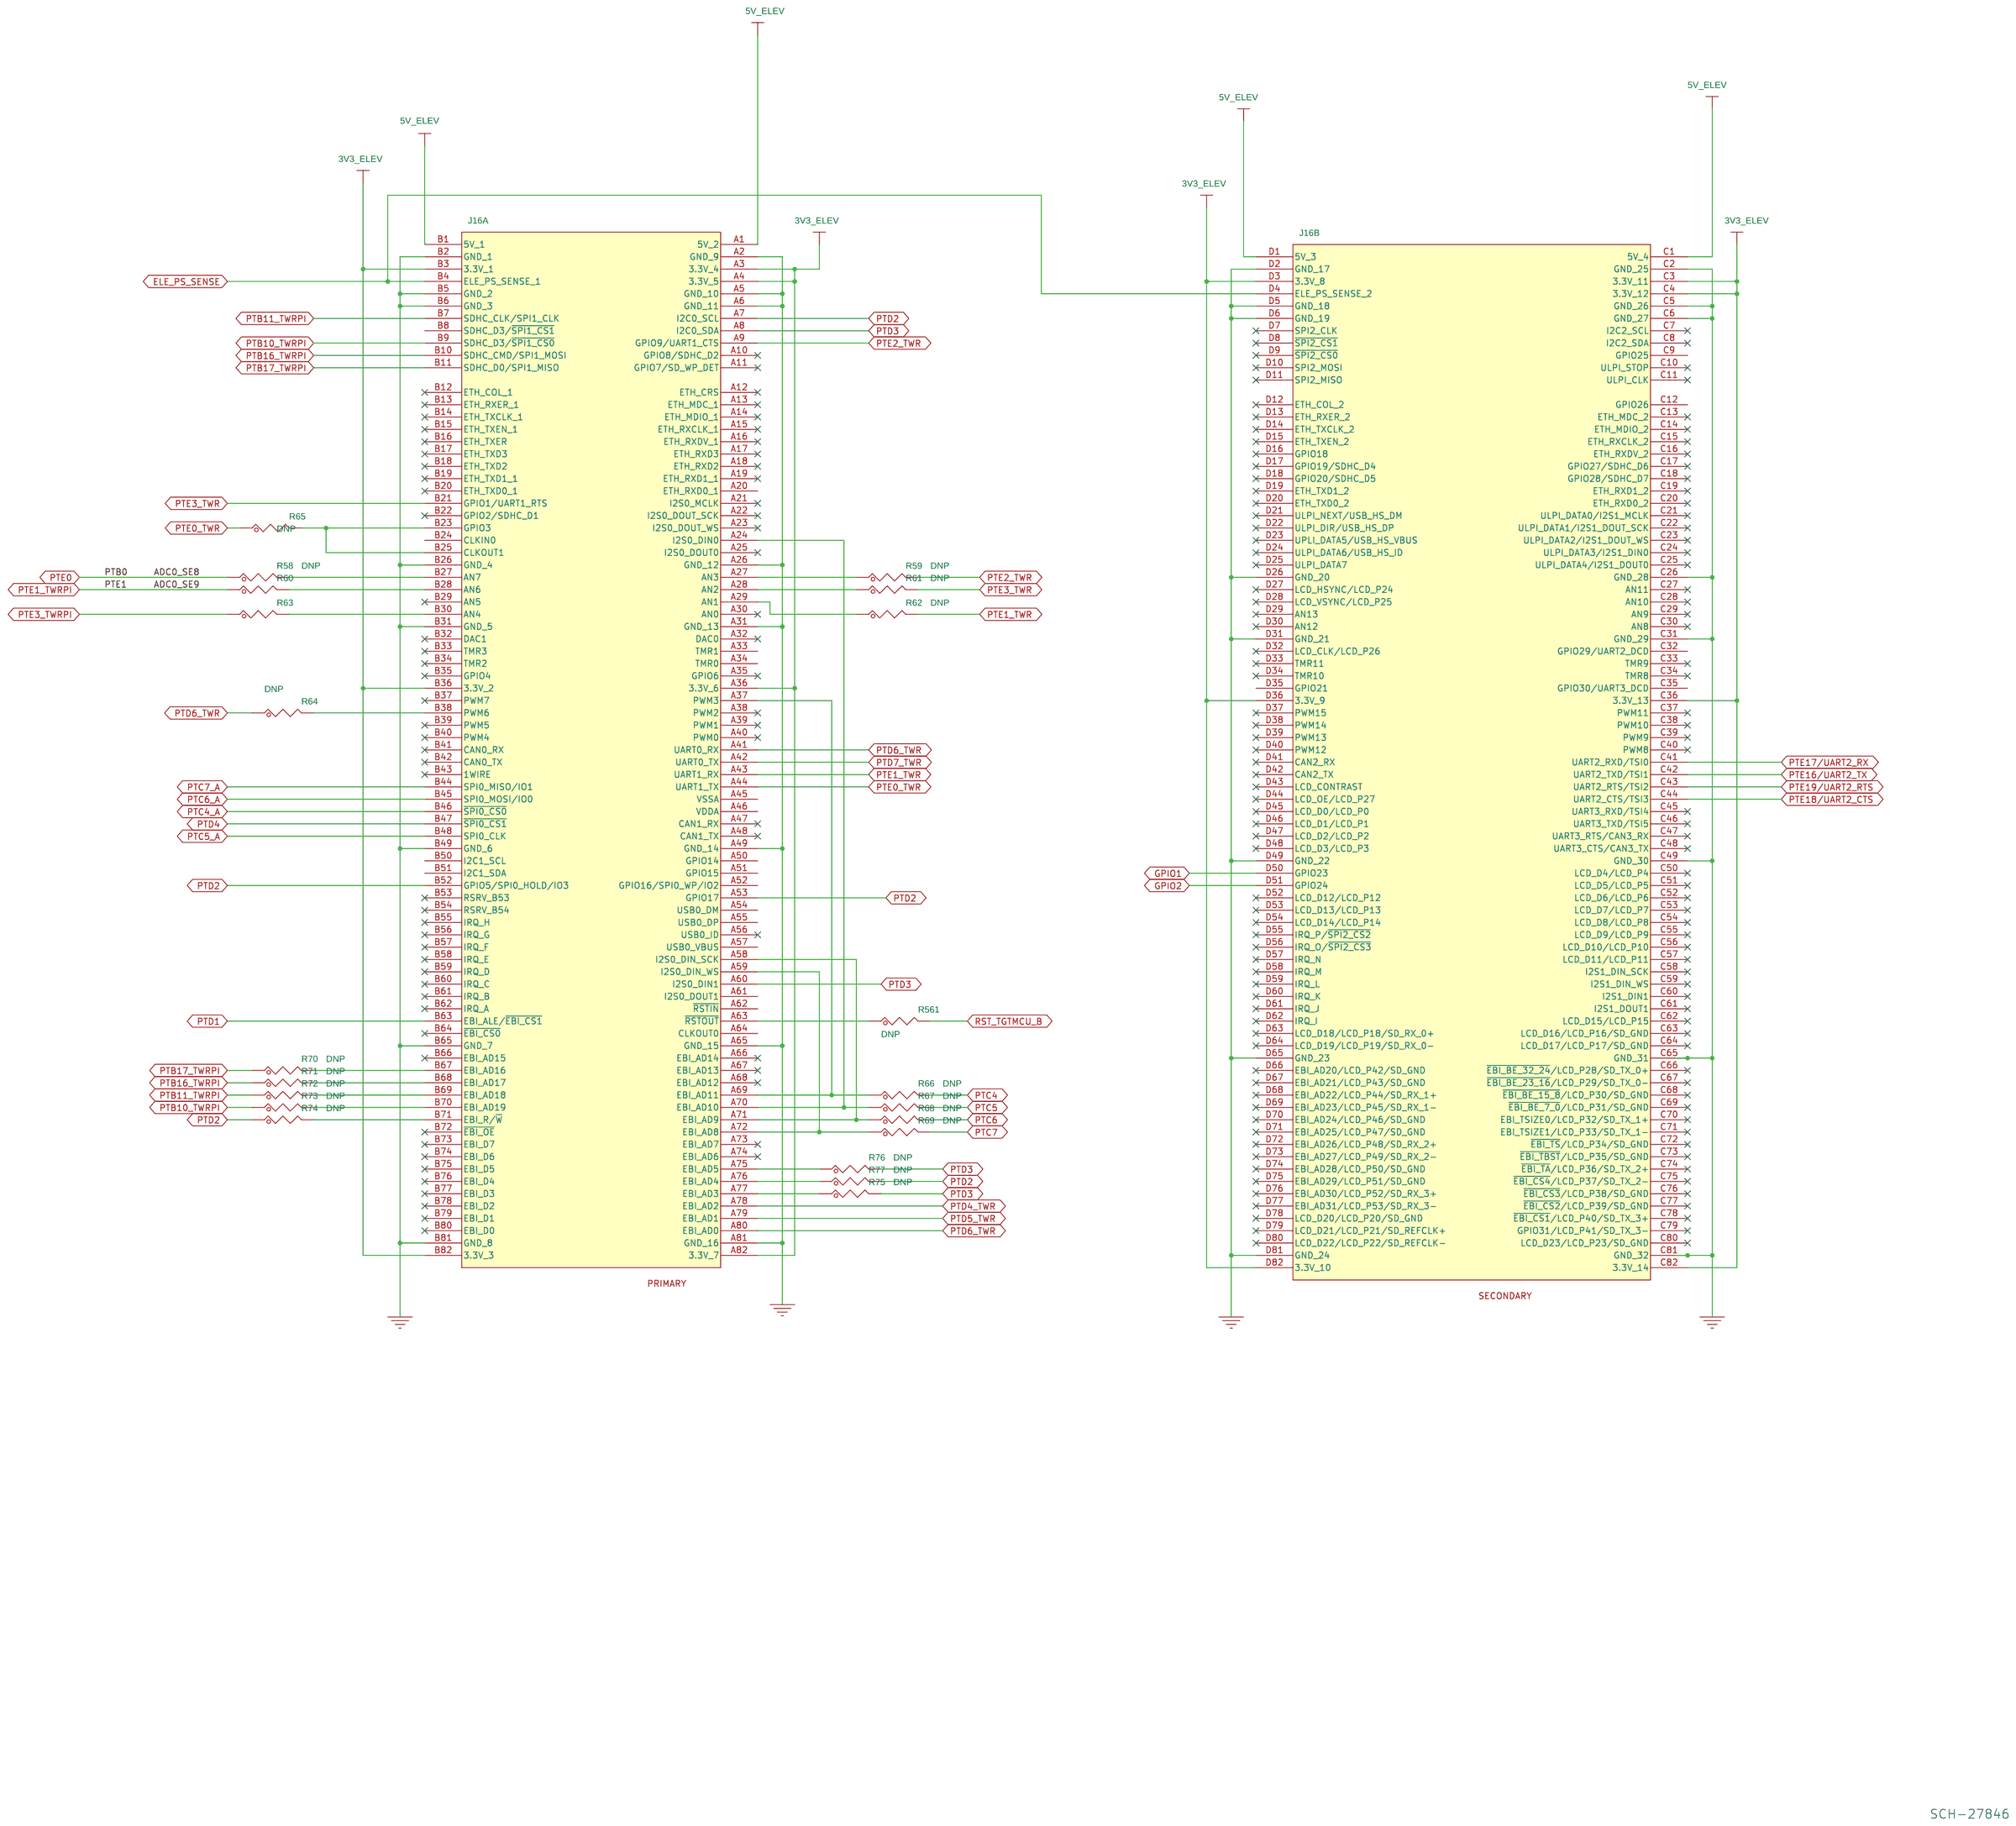
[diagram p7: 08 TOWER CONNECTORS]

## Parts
sheet 06 PERIPHERALS
D5  BLUE  [led2_2p34_2p1x1p25]
D6  BLUE  [led2_2p34_2p1x1p25]
D7  BLUE  [led2_2p34_2p1x1p25]
D8  BLUE  [led2_2p34_2p1x1p25]
J8  HDR 1X2 TH  [HDR102]
J9  CON_2X10  [con_tfm_20m_50_sm]
J10  CON_2X10  [con_tfm_20m_50_sm]
J17  HDR 3X4  [hdr304]
J18  HDR 3X4  [hdr304]
J19  HDR TH 1X3  [HDR103]
J20  HDR TH 1X3  [HDR103]
J21  HDR TH 1X3  [HDR103]
J24  HDR TH 1X3  [HDR103]
R16  390  [RC0402_25]
R17  390  [RC0402_25]
R18  390  [RC0402_25]
R19  390  [RC0402_25]
R20  0  [RC0402_25]
R21  4.7K  [RC0402_25]
R22  4.7K  [RC0402_25]
R23  10.0K  [RC0402_25]
R24  10.0K  [RC0402_25]
R552  10.0K  [RC0402_25]
R553  10.0K  [RC0402_25]
R554  10.0K  [RC0402_25]
R555  10.0K  [RC0402_25]
R563  10.0K  [RC0402_25]
R564  0  [RC0402_25]
R565  10.0K  [RC0402_25]
R566  0  [RC0402_25]
SW1  PB switch  [SW4_4MM]
SW2  PB switch  [SW4_4MM]
SW3  PB switch  [SW4_4MM]
SW4  PB switch  [SW4_4MM]
TP14  TPAD_040  [TPAD_040]
TP15  TPAD_040  [TPAD_040]
TP16  TPAD_040  [TPAD_040]
TP17  TPAD_040  [TPAD_040]
TP500  TPAD_040  [TPAD_040]
TP501  TPAD_040  [TPAD_040]
TP502  TPAD_040  [TPAD_040]
TP504  TPAD_040  [TPAD_040]
TP506  TPAD_040  [TPAD_040]
U13  AT45DB161E-SSHD  [SO8_1P27_4X5]
sheet 07 OpenSDA
C26  1.0UF  [CC0402_25]
C29  0.1UF  [CC0402_25]
C30  22PF  [CC0402_25]
C31  22PF  [CC0402_25]
C32  2.2UF  [CC0603_OV]
C33  0.1UF  [CC0402_25]
C34  18PF  [CC0603_OV]
C49  1.0UF  [CC0402_25]
D9  ORANGE  [LED_0603]
D11  LED GREEN  [LED_0603]
D12  MSS1P3L  [smb_2p7x1p4]
D13  MSS1P3L  [smb_2p7x1p4]
D16  CDSQR400B  [sod-923f]
J11  HDR_19P  [con_ftsh_19m_50_sm]
J12  HDR 1X2 TH  [HDR102]
J13  HDR 2X5  [CON_2RH_10_50]
J15  CONN USB MINI-B  [con5_usb_ra_smt]
J29  HDR 1X2  [hdr102]
J30  HDR 1X2  [hdr102]
L6  330 OHM  [IND_0805]
L7  330 OHM  [IND_0805]
Q2  MMBT2484L  [SOT23]
R25  10.0K  [RC0402_25]
R26  10.0K  [RC0402_25]
R27  0  [RC0402_25]
R46  330  [RC0402_25]
R50  33  [RC0402_25]
R51  33  [RC0402_25]
R52  4.7K  [RC0603_OV]
R88  1.0K  [RC0402_25]
R89  1.0K  [RC0402_25]
R90  1.0K  [RC0402_25]
R91  1.0K  [RC0402_25]
R92  1.0K  [RC0402_25]
R93  1.0K  [RC0402_25]
R94  0  [RC0402_25]
R95  0  [RC0402_25]
R100  10K  [RC0603_OV]
R104  220  [RC0603_OV]
R105  10K  [RC0603_OV]
R106  27K  [RC0402_25]
R107  10K  [RC0603_OV]
R108  10.0K  [RC0402_25]
R109  15K  [RC0402_25]
R110  10.0K  [RC0402_25]
R111  1K  [RC0402_25]
R112  27K  [RC0402_25]
R551  1.0K  [RC0402_25]
R560  10K  [RC0603_OV]
R562  100K  [RC0402_25]
SW6  PB switch  [SW4_4MM]
TP100  TPAD_030  [TPAD_030]
TP101  TPAD_030  [TPAD_030]
TP102  TPAD_030  [TPAD_030]
TP103  TPAD_030  [TPAD_030]
TP104  TPAD_040  [TPAD_040]
TP105  TPAD_030  [TPAD_030]
TP106  TPAD_030  [TPAD_030]
TP107  TPAD_030  [TPAD_030]
TP108  TPAD_030  [TPAD_030]
TP508  TPAD_030  [TPAD_030]
TP509  TPAD_030  [TPAD_030]
TP510  TPAD_030  [TPAD_030]
TP511  TPAD_030  [TPAD_030]
TP512  TPAD_030  [TPAD_030]
U4  74LVC125ADB  [ssop14]  (sections A,B,C,D)
U6  PK20DX128VFM5  [QFN32_S142EP]
U7  MIC2005-0.8YM6  [SOT23-6_a]
U8  GSOT05C-GS08  [sot23_a]
U14  TXS0101  [SOT23-6]
Y3  8MHZ  [xtlosc4_5x3MM_sm]
sheet 08 TOWER CONNECTORS
J16  PCI EXPRESS TOWER SYSTEM  [cn2x82_finger_ass]  (sections A,B)
R58  0  [RC0402_25]
R59  0  [RC0402_25]
R60  0  [RC0402_25]
R61  0  [RC0402_25]
R62  0  [RC0402_25]
R63  0  [RC0402_25]
R64  0  [RC0402_25]
R65  0  [RC0402_25]
R66  0  [RC0402_25]
R67  0  [RC0402_25]
R68  0  [RC0402_25]
R69  0  [RC0402_25]
R70  0  [RC0402_25]
R71  0  [RC0402_25]
R72  0  [RC0402_25]
R73  0  [RC0402_25]
R74  0  [RC0402_25]
R75  0  [RC0402_25]
R76  0  [RC0402_25]
R77  0  [RC0402_25]
R561  0  [RC0402_25]
sheet MOHAVE
ANT1  F_Antenna  [f_antenna_dig528-2]
C7  0.33UF  [CC0402_25]
C8  5pF  [CC0402_25]
C9  1000pF  [CC0402_25]
C10  5pF  [CC0402_25]
C11  1000pF  [CC0402_25]
C12  0.1UF  [CC0402_25]
C13  0.1UF  [CC0402_25]
C14  0.1UF  [CC0402_25]
C15  33PF  [CC0402_25]
C16  0.33UF  [CC0402_25]
C17  10PF  [CC0402_25]
C18  10PF  [CC0402_25]
C19  1.8pF  [CC0402_25]
C20  10PF  [CC0402_25]
C21  12PF  [CC0402_25]
C22  12PF  [CC0402_25]
C23  12PF  [CC0402_25]
C24  12PF  [CC0402_25]
C25  1PF  [CC0402_25]
C27  2.2UF  [CC0603_OV]
C28  0.1UF  [CC0402_25]
C35  47PF  [CC0402_25]
C36  0.1UF  [CC0402_25]
C42  0.1UF  [CC0402_25]
C43  1000pF  [CC0402_25]
C44  5pF  [CC0402_25]
C45  10PF  [CC0402_25]
C46  1000pF  [CC0402_25]
C47  5pF  [CC0402_25]
C48  47PF  [CC0402_25]
C50  1.0UF  [CC0402_25]
D14  MSS1P3L  [smb_2p7x1p4]
D15  MSS1P3L  [smb_2p7x1p4]
J4  SMA  [CON_SMA_EDGE_062]
J5  HDR 1X2  [hdr102]
J6  MICRO USB AB 5  [con5_microusb]
J27  HDR 1X2 TH  [HDR102]
L2  0  [RC0603_OV]
L3  0  [RC0603_OV]
L4  330 OHM  [IND_0805]
L5  2.2nH  [IND_0402]
L8  330 OHM  [IND_0805]
R12  1.0M  [RC0603_OV]
R13  0  [RC0402_25]
R14  0  [RC0402_25]
R15  0  [RC0402_25]
R33  33  [RC0603_OV]
R34  33  [RC0603_OV]
R78  0  [RC0402_25]
R79  0  [RC0402_25]
R80  0  [RC0402_25]
R81  0  [RC0402_25]
R82  0  [RC0402_25]
R83  0  [RC0402_25]
R84  0  [RC0402_25]
R85  0  [RC0402_25]
R86  0  [RC0402_25]
R87  0  [RC0402_25]
TP21  TPAD_040  [TPAD_040]
TP22  TPAD_040  [TPAD_040]
TP25  TESTLOOP_BLACK  [tp_th_063]
TP26  TESTLOOP_BLACK  [tp_th_063]
TP27  TPAD_040  [TPAD_040]
U3  MKW21D256V  [LGA63_0P5_8X8]
U10  0402ESDA-MLP  [0402_mlp]
U11  0402ESDA-MLP  [0402_mlp]
U12  0402ESDA-MLP  [0402_mlp]
Y1  32MHZ  [xtlosc4_3p2x2p5mm_sm]
Y2  32.768KHZ  [XTAL2-3p2x1p5-SM]
Z1  2400MHz 50OHM  [XFMR_HHM1525_2x1_25mm_6P]
sheet POWER SUPPLY
C1  10UF  [CC0805_OV]
C2  10UF  [CC0805_OV]
C3  10UF  [CC0805_OV]
C4  0.1UF  [CC0402_25]
D1  MBR0520LT1G  [SOD123]
D2  MBR0520LT1G  [SOD123]
D3  MBR0520LT1G  [SOD123]
D4  GREEN  [LED0805]
J1  HDR 2X3  [HDR203]
J2  HDR 2X3  [HDR203]
J3  HDR TH 1X3  [HDR103]
J28  HDR 1X2  [hdr102]
L1  3.3uH  [ind_ihlp_2020]
Q1  SI2305  [SOT-23]
R1  0  [RC0402_25]
R2  0  [RC0402_25]
R4  0  [RC0402_25]
R5  200K  [RC0402_25]
R6  0  [RC0402_25]
R7  4.7K  [RC0402_25]
R8  0  [RC0402_25]
R9  10K  [RC0402_25]
R10  330  [RC0402_25]
SW5  DPDT SWITCH  [sw_6p_11x7p31mm]
TL1  TESTLOOP  [testpoint_135_070mil]
TL2  TESTLOOP  [testpoint_135_070mil]
TL3  TESTLOOP  [testpoint_135_070mil]
TP1  TPAD_040  [TPAD_040]
TP2  TPAD_040  [TPAD_040]
TP3  TPAD_040  [TPAD_040]
TP4  TPAD_040  [TPAD_040]
TP5  TPAD_040  [TPAD_040]
TP6  TPAD_040  [TPAD_040]
TP7  TPAD_040  [TPAD_040]
TP9  TPAD_040  [TPAD_040]
TP10  TPAD_040  [TPAD_040]
TP11  TPAD_040  [TPAD_040]
TP12  TPAD_040  [TPAD_040]
TP507  TESTLOOP_BLACK  [tp_th_063]
U1  TPS63001  [qfn_10_0p5_3x3]

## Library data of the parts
D5-D8 = LED: LED BLUE SGL 20MA SMT 0805; AGILE_PN: 370-76451; CAD_APPROVED: Yes; HEIGHT: 0.9MM; MFG_NAME01: LITE ON; MFG_PN01: LTST-C171TBKT; ROHS: Yes
J8 J12 = CONN_HDR_2X1: HDR 1X2 TH 100MIL SP 339H AU 98L; AGILE_PN: 210-75439; CAD_APPROVED: YES; HEIGHT: 8.71 MM; MFG_NAME01: SAMTEC; MFG_PN01: TSW-102-07-G-S; ROHS: Yes
J9 J10 = CONN_SHRHDR_10X2: CON 2X10 PLUG SHRD SMT 50MIL CTR 237H AU; AGILE_PN: 211-78839; CAD_APPROVED: Yes; HEIGHT: 6.02 MM; MFG_NAME01: SAMTEC; MFG_PN01: TFC-110-02-L-D-A-K; ROHS: Yes
J17 J18 = HDR_3X4: HDR 3X4 TH 100MIL CTR 338H AU 100L; AGILE_PN: 210-79771; CAD_APPROVED: Yes; HEIGHT: 8.58MM; MFG_NAME01: SAMTEC; MFG_PN01: HTSW-104-07-G-T; ROHS: Yes
J3 J19-J21 J24 = CONN_HDR_3X1: HDR 1X3 TH 100MIL SP 339H AU 100L; AGILE_PN: 210-75726; CAD_APPROVED: Yes; HEIGHT: 8.65MM; MFG_NAME01: SAMTEC; MFG_PN01: TSW-103-07-G-S; ROHS: Yes
R16-R19 = RES: RES MF 390 OHM 1/16W 5% 0402; AGILE_PN: 470-75624; CAD_APPROVED: Yes; FPLIST: RC0402_25,RC0402_HD,0402_CC; MFG_NAME01: VISHAY INTERTECHNOLOGY; MFG_PN01: CRCW0402390RJNED; ROHS: Yes; Tolerance: 5%
R1 R2 R4 R6 R8 R15 R20 R60 R63 R78-R82 R84-R87 = RES: RES MF ZERO OHM 1/16W 5% 0402; AGILE_PN: 470-75394; CAD_APPROVED: Yes; FPLIST: RC0402_25,RC0402_HD,RC0402_X2,0402_CC; MFG_NAME01: ROHM; MFG_PN01: MCR01MZPJ000; ROHS: Yes; Tolerance: 5%
R7 R21 R22 = RES: RES MF 4.7K 1/16W 5% 0402; AGILE_PN: 470-75626; CAD_APPROVED: Yes; FPLIST: RC0402_25,RC0402_HD,0402_CC; MFG_NAME01: YAGEO AMERICA; MFG_PN01: RC0402JR-074K7L; ROHS: Yes; Tolerance: 5%
R23-R26 R110 = RES: RES MF 10.0K 1/16W 1% AEC-Q200 0402; AGILE_PN: 470-75416; CAD_APPROVED: Yes; FPLIST: RC0402_25,RC0402_HD,0402_CC; HEIGHT: 0.4MM; MFG_NAME01: VISHAY INTERTECHNOLOGY; MFG_PN01: CRCW040210K0FKED; ROHS: Yes; TOL: 1%; Tolerance: 1%
R552-R555 = RES: RES MF 10.0K 1/16W 1% AEC-Q200 0402; AGILE_PN: 470-75416; ASSY_OPT: DNP; CAD_APPROVED: Yes; FPLIST: RC0402_25,RC0402_HD,0402_CC; HEIGHT: 0.4MM; MFG_NAME01: VISHAY INTERTECHNOLOGY; MFG_PN01: CRCW040210K0FKED; ROHS: Yes; SIGNAL_MODEL: DEFAULT_RESISTOR_10000OHM_2_1; TOL: 1%; Tolerance: 1%
R563 R565 = RES: RES MF 10.0K 1/16W 1% AEC-Q200 0402; AGILE_PN: 470-75416; CAD_APPROVED: Yes; FPLIST: RC0402_25,RC0402_HD,0402_CC; HEIGHT: 0.4MM; MFG_NAME01: VISHAY INTERTECHNOLOGY; MFG_PN01: CRCW040210K0FKED; ROHS: Yes; SIGNAL_MODEL: DEFAULT_RESISTOR_10000OHM_2_1; TOL: 1%; Tolerance: 1%
R27 R58 R59 R61 R62 R64-R77 R83 R561 R564 R566 = RES: RES MF ZERO OHM 1/16W 5% 0402; AGILE_PN: 470-75394; ASSY_OPT: DNP; CAD_APPROVED: Yes; FPLIST: RC0402_25,RC0402_HD,RC0402_X2,0402_CC; MFG_NAME01: ROHM; MFG_PN01: MCR01MZPJ000; ROHS: Yes; Tolerance: 5%
SW1-SW4 SW6 = SW_TACT-SPST-2_SM: SW SMT 4.0MM FMS 0.1A MAX 16V MAX ROHS COMPLIANT; AGILE_PN: 510-75078; CAD_APPROVED: Yes; HEIGHT: 4.19 MM; MFG_NAME01: BOURNS; MFG_PN01: 7914J-1-000E; ROHS: Yes
TP1-TP7 TP9-TP12 TP14-TP17 TP21 TP22 TP27 TP104 = TestLoop: TEST POINT PAD 40MIL DIA SMT, NO PART TO ORDER; AGILE_PN: 211-76643; CAD_APPROVED: Yes; HEIGHT: 0.1MM; MFG_NAME01: NOTACOMPONENT; MFG_PN01: NOTACOMPONENT; ROHS: Yes
TP500-TP502 TP504 TP506 = TESTLOOP: TEST POINT PAD 40MIL DIA SMT, NO PART TO ORDER; AGILE_PN: 211-76643; CAD_APPROVED: Yes; HEIGHT: 0.1MM; MFG_NAME01: NOTACOMPONENT; MFG_PN01: NOTACOMPONENT; ROHS: Yes
U13 = AT45DB041D-SU: IC FLASH 16MBIT 85MHZ 2.5-3.6V SOIC8; AGILE_PN: 342-00525; CAD_APPROVED: Yes; HEIGHT: 1.75MM; MFG_NAME01: ATMEL; MFG_PN01: AT45DB161E-SSHD-T; ROHS: Yes
C26 C49 C50 = CAP_NP: CAP CER 1.0UF 10V 10% X5R 0402; AGILE_PN: 150-75772; CAD_APPROVED: Yes; FPLIST: CC0402_25,CC0402_HD,0402_CC; HEIGHT: 0.6MM; MFG_NAME01: YAGEO AMERICA; MFG_PN01: CC0402KRX5R6BB105; ROHS: Yes; VOLTAGE: 10V
C4 C12-C14 C29 C42 = CAP_NP: CAP CER 0.1UF 16V 10% X7R 0402; AGILE_PN: 150-75182; CAD_APPROVED: Yes; FPLIST: CC0402_25,CC0402_HD,0402_CC; HEIGHT: 0.635MM; MFG_NAME01: KEMET; MFG_PN01: C0402C104K4RAC; ROHS: Yes; Tolerance: 10%; VOLTAGE: 16V
C30 C31 = CAP_NP: CAP CER 22PF 50V 5% C0G 0402; AGILE_PN: 150-75266; ASSY_OPT: DNP; CAD_APPROVED: Yes; FPLIST: CC0402_25,CC0402_HD,0402_CC; HEIGHT: 0.635MM; MFG_NAME01: AVX; MFG_PN01: 04025A220JAT2A; ROHS: Yes; Tolerance: 5%; VOLTAGE: 50V
C32 = CAP_NP: CAP CER 2.2UF 10V 10% X7R 0603; AGILE_PN: 150-78564; CAD_APPROVED: Yes; FPLIST: CC0603_OV,CC0603,0603_CC; HEIGHT: 1.25MM; MFG_NAME01: TAIYO YUDEN; MFG_PN01: LMK107B7225KA-T; ROHS: Yes; Tolerance: 10%; VOLTAGE: 10V
C33 = CAP_NP: CAP CER 0.1UF 10V 10% X5R 0402; AGILE_PN: 150-75634; CAD_APPROVED: Yes; FPLIST: CC0402_25,CC0402_HD,0402_CC; HEIGHT: 0.64MM; MFG_NAME01: KEMET; MFG_PN01: C0402C104K8PAC; ROHS: Yes; TOL: 10%; Tolerance: 10%; VOLTAGE: 10V
C34 = CAP_NP: CAP CER 18PF 50V 5% C0G 0603; AGILE_PN: 150-75116; ASSY_OPT: DNP; CAD_APPROVED: Yes; FPLIST: CC0603_OV,CC0603,0603_CC; HEIGHT: 0.90MM; MFG_NAME01: YAGEO AMERICA; MFG_PN01: CC0603JRNPO9BN180; ROHS: Yes; TOL: 5%; Tolerance: 5%; VOLTAGE: 50V
D9 = LED: LED ULTRA BRIGHT ORANGE 20MA 2V SMT 0603; AGILE_PN: 370-75080; CAD_APPROVED: Yes; HEIGHT: 0.8MM; MFG_NAME01: LITE ON; MFG_PN01: LTST-C190KFKT; ROHS: Yes
D11 = LED: LED GRN SGL 20MA 0603; AGILE_PN: 370-76565; CAD_APPROVED: Yes; HEIGHT: 0.67MM; MFG_NAME01: osram; MFG_PN01: LG L29K-G2J1-24-Z; ROHS: Yes
D12-D15 = DIODE_SCHTKY: DIODE SCH 1A 20V MICROSMP SMT; AGILE_PN: 480-76978; CAD_APPROVED: Yes; HEIGHT: 0.73MM; MFG_NAME01: VISHAY INTERTECHNOLOGY; MFG_PN01: MSS1P3L-M3/89A; ROHS: Yes
D16 = DIODE: DIODE SW 0.1A 80V SOD-923F; AGILE_PN: TMP-WF-20264; CAD_APPROVED: Yes; HEIGHT: 0.55MM; MFG_NAME01: COMCHIP TECHNOLOGY CO., LTD; PRE_APN: 480-78528; ROHS: Yes
J11 = CONN_HDR_19: HDR 19P SMT 1.27MM SP 285H AU; AGILE_PN: 211-79023; CAD_APPROVED: Yes; HEIGHT: 7.3MM; MFG_NAME01: SAMTEC; MFG_PN01: ASP-159234-02; ROHS: Yes
J13 = CONN_HDR_5X2: CONN,HEAD,2X5,STR,50/50 CON-2RH-10-50; AGILE_PN: 210-07961-00; CAD_APPROVED: Yes; HEIGHT: 3.91 MM; MFG_NAME01: SAMTEC; MFG_PN01: FTS-105-01-F-D; ROHS: Yes
J15 = USB_MINI_AB_RECEPTACLE: CON 5 USB_MINI_B_RECEPTACLE RA SMT 0.8MM 168H AU; AGILE_PN: 211-79254; CAD_APPROVED: Yes; HEIGHT: 4.27MM; MFG_NAME01: TE Connectivity Ltd; MFG_PN01: 1734035-2; ROHS: Yes
J5 J28-J30 = CONN_HDR_2X1: HDR 1X2 TH 100MIL SP 330H SN 115L; AGILE_PN: 210-76752; CAD_APPROVED: Yes; HEIGHT: 8.58MM; MFG_NAME01: Samtec; MFG_PN01: TSW-102-23-T-S; ROHS: Yes
L4 L6 L7 = BEAD: IND FER BEAD 330OHM@100MHZ 2.5A -- SMT; AGILE_PN: 180-30021; CAD_APPROVED: YES; HEIGHT: 1.05 MM; MFG_NAME01: TDK; MFG_PN01: MPZ2012S331A; PART_TYPE: FERRITE; ROHS: Yes; Tolerance: 25%
Q2 = NPN: TRAN NPN LOW NOISE 60V 100MA SOT23; AGILE_PN: 480-75151; CAD_APPROVED: Yes; HEIGHT: 1.11 MM; MFG_NAME01: ON SEMICONDUCTOR; MFG_PN01: MMBT2484LT1G; ROHS: Yes
R46 = RES: RES MF 330 OHM 1/16W 1% AEC-Q200 0402; AGILE_PN: 470-76465; CAD_APPROVED: Yes; FPLIST: RC0402_25,RC0402_HD,0402_CC; HEIGHT: 0.4MM; MFG_NAME01: VISHAY INTERTECHNOLOGY; MFG_PN01: CRCW0402330RFK; ROHS: Yes; TOL: 1%; Tolerance: 1%
R50 R51 = RES: RES MF 33.0 OHM 1/16W 1% 0402; AGILE_PN: 470-75790; CAD_APPROVED: Yes; FPLIST: RC0402_25,RC0402_HD,RC0402_X2,0402_CC; MFG_NAME01: THYE MING TECH CO LTD; MFG_PN01: CR-02FL6---33R; ROHS: Yes; Tolerance: 1%
R52 = RES: RES MF 4.7K 1/10W 5% 0603; AGILE_PN: 470-75414; CAD_APPROVED: Yes; FPLIST: RC0603_OV,RC0603,0603_CC; MFG_NAME01: VISHAY INTERTECHNOLOGY; MFG_PN01: CRCW06034K70JNEA; ROHS: Yes; Tolerance: 5%
R88-R93 R551 = RES: RES MF 1.0K 1/16W 1% 0402; AGILE_PN: 470-76037; CAD_APPROVED: Yes; FPLIST: RC0402_25,RC0402_HD,RC0402_X2,0402_CC; HEIGHT: 0.4MM; MFG_NAME01: YAGEO AMERICA; MFG_PN01: RC0402FR-071KL; ROHS: Yes; TOL: 1%; Tolerance: 1%
R13 R14 R94 R95 = RES: RES TF ZERO  OHM 1/16W AEC-Q200 RC0402; AGILE_PN: 470-75366; CAD_APPROVED: Yes; FPLIST: RC0402_25,RC0402_HD,0402_CC; MFG_NAME01: VISHAY INTERTECHNOLOGY; MFG_PN01: CRCW04020000ZS; ROHS: Yes; Tolerance: 5%
R100 R105 R107 R560 = RES: RES MF 10K 1/10W 5% 0603; AGILE_PN: 470-75410; CAD_APPROVED: Yes; FPLIST: RC0603_OV,RC0603,0603_CC; MFG_NAME01: KOA SPEER; MFG_PN01: RK73B1JTTD103J; ROHS: Yes; Tolerance: 5%
R104 = RES: RES MF 220 OHM 1/10W 5% 0603; AGILE_PN: 470-30297; CAD_APPROVED: Yes; FPLIST: RC0603_OV,RC0603,0603_CC; MFG_NAME01: KOA SPEER; MFG_PN01: RK73B1JTTD221J; ROHS: Yes; Tolerance: 5%
R106 = RES: RES MF 27K 1/16W 5% 0402; AGILE_PN: 470-76069; CAD_APPROVED: Yes; FPLIST: RC0402_25,RC0402_HD,0402_CC; MFG_NAME01: VISHAY INTERTECHNOLOGY; MFG_PN01: CRCW040227K0JNED; ROHS: Yes; Tolerance: 5%
R108 = RES: RES MF 10.0K 1/16W 1% AEC-Q200 0402; AGILE_PN: 470-75416; ASSY_OPT: DNP; CAD_APPROVED: Yes; FPLIST: RC0402_25,RC0402_HD,0402_CC; HEIGHT: 0.4MM; MFG_NAME01: VISHAY INTERTECHNOLOGY; MFG_PN01: CRCW040210K0FKED; ROHS: Yes; TOL: 1%; Tolerance: 1%
R109 = RES: RES MF 15.0K 1/16W 1% 0402; AGILE_PN: 470-76066; CAD_APPROVED: Yes; FPLIST: RC0402_25,RC0402_HD,0402_CC; HEIGHT: 0.4 MM; MFG_NAME01: BOURNS; MFG_PN01: CR0402-FX-1502GLF; ROHS: Yes; TOL: 1%; Tolerance: 1%
R111 = RES: RES MF 1.0K 1/16W 5% 0402; AGILE_PN: 470-75555; CAD_APPROVED: Yes; FPLIST: RC0402_25,RC0402_HD,RC0402_X2,0402_CC; HEIGHT: 0.41mm; MFG_NAME01: VISHAY INTERTECHNOLOGY; MFG_PN01: CRCW04021K00JNED; ROHS: Yes; TOL: 5%; Tolerance: 5%
R112 = RES: RES MF 27K 1/16W 5% 0402; AGILE_PN: 470-76069; ASSY_OPT: DNP; CAD_APPROVED: Yes; FPLIST: RC0402_25,RC0402_HD,0402_CC; MFG_NAME01: VISHAY INTERTECHNOLOGY; MFG_PN01: CRCW040227K0JNED; ROHS: Yes; Tolerance: 5%
R562 = RES: RES MF 100K 1/16W 1% 0402; AGILE_PN: 470-76240; CAD_APPROVED: Yes; FPLIST: RC0402_25,RC0402_HD,0402_CC; MFG_NAME01: YAGEO AMERICA; MFG_PN01: RC0402FR-07100KL; ROHS: Yes; Tolerance: 1%
TP100-TP103 TP107 TP108 TP508-TP512 = TESTLOOP: TEST POINT PAD 30MIL DIA SMT, NO PART TO ORDER; AGILE_PN: 211-76642; CAD_APPROVED: Yes; HEIGHT: 0.1MM; MFG_NAME01: NOTACOMPONENT; MFG_PN01: NOTACOMPONENT; ROHS: Yes
TP105 TP106 = TestLoop: TEST POINT PAD 30MIL DIA SMT, NO PART TO ORDER; AGILE_PN: 211-76642; CAD_APPROVED: Yes; HEIGHT: 0.1MM; MFG_NAME01: NOTACOMPONENT; MFG_PN01: NOTACOMPONENT; ROHS: Yes
U4 = 74-125_14P: IC BUF QUAD TS 1.2-3.6V SSOP14; AGILE_PN: 312-79933; CAD_APPROVED: Yes; HEIGHT: 2mm; MFG_NAME01: NXP SEMICONDUCTORS; ROHS: Yes
U6 = PK20DX128V_QFN_32P: IC MCU FLASH 128KB 50MHZ 1.71-3.6V QFN32; AGILE_PN: 344-01231; CAD_APPROVED: Yes; HEIGHT: 1MM; MFG_NAME01: FREESCALE SEMICONDUCTOR; MFG_PN01: MK20DX128VFM5; ROHS: Yes
U7 = MIC2005-0.8YM6: IC LIN SW PWR 0.8A 2.5-5.5V SOT23-6; AGILE_PN: 315-79199; CAD_APPROVED: Yes; HEIGHT: 1.45MM; MFG_NAME01: MICREL; ROHS: Yes
U8 = DIODE_2LINE_ESD: DIODE ESD 2LINE 5V SOT23; AGILE_PN: 480-78313; CAD_APPROVED: Yes; HEIGHT: 1.15MM; MFG_NAME01: VISHAY INTERTECHNOLOGY; ROHS: Yes
U14 = TXB0101_6P: IC VXLTR 1BIT 1.65-3.6V/2.3-5.5V SOT23-6; AGILE_PN: 315-79596; CAD_APPROVED: Yes; HEIGHT: 1.45 MM; MFG_NAME01: TEXAS INSTRUMENTS; MFG_PN01: TXS0101DBVR; ROHS: Yes
Y3 = CRYSTAL_JXS63: XTAL 8MHZ 20PPM PAR 18PF ESR 200OHM SMT; AGILE_PN: 230-77754; CAD_APPROVED: Yes; HEIGHT: 1.1MM; MFG_NAME01: Abracon Corporation; MFG_PN01: ABM3B-8.000MHZ-B2-T; ROHS: Yes
J16 = CONN_PCI_XPRESS_X16_328P: CON DUAL 2X82 Edge PCI Express SMT 1MM SP 591H FOR TOWER SYSTEM NOT A PART TO ORDER; AGILE_PN: 211-78844; CAD_APPROVED: Yes; Group: a; HEIGHT: 15.01MM; MFG_NAME01: NA; MFG_PN01: EDGE PCI EXPRESS 164; ROHS: Yes
ANT1 = F_Antenna: PCB F ANTENNA, NO PART ORDER; AGILE_PN: 510-75678; CAD_APPROVED: Yes; HEIGHT: 0MM; MFG_NAME01: NOT A PART; MFG_PN01: NOT A PART; ROHS: Yes
C7 C16 = CAP_NP: CAP CER 0.33UF 6.3V 10% X5R 0402; AGILE_PN: 150-77381; CAD_APPROVED: Yes; FPLIST: CC0402_25,CC0402_HD,0402_CC; HEIGHT: 0.55 MM; MFG_NAME01: muRata; MFG_PN01: GRM155R60J334KE01D; ROHS: Yes; Tolerance: 10%
C8 C10 C44 C47 = CAP_NP: CAP CER 5pF 50V 5% C0G 0402; AGILE_PN: 150-79097; CAD_APPROVED: Yes; FPLIST: CC0402_25,CC0402_HD,0402_CC; HEIGHT: 0.55 MM; MFG_NAME01: MURATA; MFG_PN01: GJM1555C1H5R0CB01D; ROHS: Yes; Tolerance: 5%; VOLTAGE: 50V
C9 C11 C43 C46 = CAP_NP: CAP CER 1000PF 50V 5% C0G 0402; AGILE_PN: 150-76334; CAD_APPROVED: Yes; FPLIST: CC0402_25,CC0402_HD,0402_CC; HEIGHT: 0.55MM; MFG_NAME01: MURATA; MFG_PN01: GRM1555C1H102JA01D; ROHS: Yes; Tolerance: 5%; VOLTAGE: 50V
C15 = CAP_NP: CAP CER 33PF 50V 5% C0G 0402; AGILE_PN: 150-30000; CAD_APPROVED: Yes; FPLIST: CC0402_25,CC0402_HD,0402_CC; HEIGHT: 0.635MM; MFG_NAME01: VENKEL COMPANY; MFG_PN01: C0402C0G500-330JNE; ROHS: Yes; Tolerance: 5%; VOLTAGE: 50VDC
C17 = CAP_NP: CAP CER 10PF 50V 5% C0G 0402; AGILE_PN: 150-75265; CAD_APPROVED: YES; FPLIST: CC0402_25,CC0402_HD,0402_CC; HEIGHT: 0.635MM; MFG_NAME01: AVX; MFG_PN01: 04025A100JAT2A; ROHS: Yes; TOL: 5%; Tolerance: 5%; VOLTAGE: 50V
C18 C20 = CAP_NP: CAP CER 10PF 50V 5% C0G 0402; AGILE_PN: 150-75265; ASSY_OPT: DNP; CAD_APPROVED: YES; FPLIST: CC0402_25,CC0402_HD,0402_CC; HEIGHT: 0.635MM; MFG_NAME01: AVX; MFG_PN01: 04025A100JAT2A; ROHS: Yes; TOL: 5%; Tolerance: 5%; VOLTAGE: 50V
C19 = CAP_NP: CAP CER 1.8PF 50V 0.25PF C0G 0402; AGILE_PN: 150-75963; CAD_APPROVED: Yes; FPLIST: CC0402_25,CC0402_HD,0402_CC; HEIGHT: 0.55MM; MFG_NAME01: MURATA; MFG_PN01: GRM1555C1H1R8CA01D; ROHS: Yes; Tolerance: 0.25pF; VOLTAGE: 50V
C21-C24 = CAP_NP: CAP CER 12PF 50V 5% C0G 0402; AGILE_PN: 150-75680; CAD_APPROVED: Yes; FPLIST: CC0402_25,CC0402_HD,0402_CC; HEIGHT: 0.55MM; MFG_NAME01: MURATA; MFG_PN01: GRM1555C1H120JZ01D; ROHS: Yes; Tolerance: 5%; VOLTAGE: 50V
C25 = CAP_NP: CAP CER 1PF 50V 5% C0G 0402; AGILE_PN: 150-76350; CAD_APPROVED: Yes; FPLIST: CC0402_25,CC0402_HD,0402_CC; HEIGHT: 0.55MM; MFG_NAME01: MURATA; MFG_PN01: GRM1555C1H1R0CA01B; ROHS: Yes; Tolerance: 5%; VOLTAGE: 50V
C27 = CAP_NP: CAP CER 2.2UF 10V 10% X7R 0603; AGILE_PN: 150-78564; ASSY_OPT: DNP; CAD_APPROVED: Yes; FPLIST: CC0603_OV,CC0603,0603_CC; HEIGHT: 1.25MM; MFG_NAME01: TAIYO YUDEN; MFG_PN01: LMK107B7225KA-T; ROHS: Yes; TOL: 10%; Tolerance: 10%; VOLTAGE: 10V
C28 = CAP_NP: CAP CER 0.1UF 10V 10% X5R 0402; AGILE_PN: 150-75634; ASSY_OPT: DNP; CAD_APPROVED: Yes; FPLIST: CC0402_25,CC0402_HD,0402_CC; HEIGHT: 0.64MM; MFG_NAME01: KEMET; MFG_PN01: C0402C104K8PAC; ROHS: Yes; TOL: 10%; Tolerance: 10%; VOLTAGE: 10V
C35 C48 = CAP_NP: CAP CER 47PF 16V 5% C0G 0402; AGILE_PN: 150-75268; ASSY_OPT: DNP; CAD_APPROVED: YES; FPLIST: CC0402_25,CC0402_HD,0402_CC; HEIGHT: 0.56MM; MFG_NAME01: AVX; MFG_PN01: 0402YA470JAT2A; ROHS: Yes; TOL: 5%; Tolerance: 5%; VOLTAGE: 16V
C36 = CAP_NP: CAP CER 0.1UF 16V 10% X7R 0402; AGILE_PN: 150-75182; ASSY_OPT: DNP; CAD_APPROVED: Yes; FPLIST: CC0402_25,CC0402_HD,0402_CC; HEIGHT: 0.635MM; MFG_NAME01: KEMET; MFG_PN01: C0402C104K4RAC; ROHS: Yes; Tolerance: 10%; VOLTAGE: 16V
C45 = CAP_NP: CAP CER 10PF 50V 5% C0G 0402; AGILE_PN: 150-75265; CAD_APPROVED: YES; FPLIST: CC0402_25,CC0402_HD,0402_CC; HEIGHT: 0.635MM; MFG_NAME01: AVX; MFG_PN01: 04025A100JAT2A; ROHS: Yes; Tolerance: 5%; VOLTAGE: 50V
J4 = SMB: CON, SMA, EDGE 0.062IN, 50 OHM FEMALE 18GHZ; AGILE_PN: 211-75291; CAD_APPROVED: Yes; HEIGHT: 4.08 MM; MFG_NAME01: JOHNSON COMPONENTS INC; MFG_PN01: 142-0701-851; ROHS: Yes
J6 = USB_MINI_AB_RECEPTACLE: CON 1X5 USB_MICRO_AB_RECEPTACLE RA SMT 0.65MM SP 105H AU; AGILE_PN: 211-78722; ASSY_OPT: DNP; CAD_APPROVED: Yes; HEIGHT: 2.65MM; MFG_NAME01: Molex; MFG_PN01: 47589-0001; ROHS: Yes
J27 = CONN_HDR_2X1: HDR 1X2 TH 100MIL SP 339H AU 98L; AGILE_PN: 210-75439; ASSY_OPT: DNP; CAD_APPROVED: YES; HEIGHT: 8.71 MM; MFG_NAME01: SAMTEC; MFG_PN01: TSW-102-07-G-S; ROHS: Yes
L2 L3 = RES: RES MF ZERO OHM 1/10W -- 0603; AGILE_PN: 470-75407; CAD_APPROVED: Yes; FPLIST: RC0603_OV,RC0603,R603-X2,0603_CC; MFG_NAME01: VISHAY INTERTECHNOLOGY; MFG_PN01: CRCW06030000Z0EA; ROHS: Yes; Tolerance: 1%
L5 = INDUCTOR: IND -- 0.0022UH@100MHZ 300MA 0.0003UH 0402; AGILE_PN: 180-76426; CAD_APPROVED: Yes; FPLIST: IND_0402,0402_CC; HEIGHT: 0.55mm; MFG_NAME01: MURATA; MFG_PN01: LQG15HS2N2S02D; ROHS: Yes; Tolerance: 0.0003UH
L8 = BEAD: IND FER BEAD 330OHM@100MHZ 2.5A -- SMT; AGILE_PN: 180-30021; CAD_APPROVED: YES; HEIGHT: 1.05 MM; MFG_NAME01: TDK; MFG_PN01: MPZ2012S331A; PART_TYPE: FERRITE; ROHS: Yes; TOL: 25%; Tolerance: 25%
R12 = RES: RES MF 1.0M 1/10W 5% 0603; AGILE_PN: 470-75846; CAD_APPROVED: Yes; FPLIST: RC0603_OV,RC0603,0603_CC; HEIGHT: 0.55MM; MFG_NAME01: BOURNS; MFG_PN01: CR0603-JW-105ELF; ROHS: Yes; TOL: 5%; Tolerance: 5%
R33 R34 = RES: RES MF 33 OHM 1/10W 5% 0603; AGILE_PN: 470-75848; CAD_APPROVED: Yes; FPLIST: RC0603_OV,RC0603,0603_CC; HEIGHT: 0.55 MM; MFG_NAME01: VISHAY INTERTECHNOLOGY; MFG_PN01: CRCW060333R0JNEA; ROHS: Yes; TOL: 5%; Tolerance: 5%
TP25 TP26 TP507 = TestLoop: TEST POINT PC MULTI PURPOSE BLK TH; AGILE_PN: 210-79450; CAD_APPROVED: Yes; HEIGHT: 8.13MM; MFG_NAME01: KEYSTONE ELECTRONICS; MFG_PN01: 5011; ROHS: Yes
U3 = MKW21D_LGA_63P: IC MCU XCVR 2.4GHZ 64KB RAM 256KB FLASH 1.8-3.6V LGA56; AGILE_PN: TMP-WF-17916; CAD_APPROVED: Yes; HEIGHT: 0.98MM; MFG_NAME01: FREESCALE SEMICONDUCTOR; MFG_PN01: MKW21D256VHA5; PRE_APN: 344-01497; ROHS: Yes
U10-U12 = DIODE_TVS_BIDIR: DIODE TVS BIDIR -- 30V 0402; AGILE_PN: 480-76179; CAD_APPROVED: Yes; HEIGHT: 0.44MM; MFG_NAME01: COOPER BUSSMANN; MFG_PN01: 0402ESDA-MLP1; ROHS: Yes
Y1 = XTAL_13Y: XTAL 32MHZ 9PF -- SMT 3.2X2.5MM; AGILE_PN: 230-77690; CAD_APPROVED: Yes; HEIGHT: 0.8MM; MFG_NAME01: NDK; MFG_PN01: EXS00A-CS02368; ROHS: Yes
Y2 = CRYSTAL: XTAL 32.768KHZ SMT ROHS COMPLIANT; AGILE_PN: 230-76374; CAD_APPROVED: Yes; HEIGHT: 0.9MM; MFG_NAME01: EPSON ELECTRONICS; MFG_PN01: FC-135 32.7680KA-A3; ROHS: Yes
Z1 = LDB_21: XFMR BALUN 2400 +/-100MHZ SMT; AGILE_PN: 560-75093; CAD_APPROVED: Yes; HEIGHT: 1.05MM; MFG_NAME01: MURATA; MFG_PN01: LDB212G4005C-001; PART_TYPE: FILTER; ROHS: Yes; Tolerance: 100MHz
C1-C3 = CAP_NP: CAP CER 10UF 10V 10% X7R 0805; AGILE_PN: 150-78501; CAD_APPROVED: Yes; FPLIST: CC0805_OV,CC0805,0805_CC; HEIGHT: 1.4MM; MFG_NAME01: Murata; MFG_PN01: GRM21BR71A106KE51L; ROHS: Yes; Tolerance: 10%; VOLTAGE: 10V
D1-D3 = DIODE_SCHTKY: DIODE SCH 0.5A 20V SOD-123; AGILE_PN: 480-75176; CAD_APPROVED: Yes; HEIGHT: 1.45MM; MFG_NAME01: ON SEMICONDUCTOR; ROHS: Yes
D4 = LED: LED GRN SGL 30MA SMT 0805; AGILE_PN: 370-76462; CAD_APPROVED: Yes; FPLIST: LED0805,LED2_0805; HEIGHT: 0.9MM; MFG_NAME01: LITE ON; MFG_PN01: LTST-C171KGKT; ROHS: Yes
J1 J2 = CONN_HDR_3X2: HDR 2X3 TH 100MIL CTR 335H AU 95L; AGILE_PN: 210-75698; CAD_APPROVED: Yes; HEIGHT: 8.5MM; MFG_NAME01: SAMTEC; MFG_PN01: TSW-103-07-S-D; ROHS: Yes
L1 = INDUCTOR: IND PWR 3.3UH@100KHZ 3.3A 20% SMT; AGILE_PN: 180-77606; CAD_APPROVED: Yes; HEIGHT: 2MM; MFG_NAME01: VISHAY INTERTECHNOLOGY; MFG_PN01: IHLP2020BZER3R3M01; PART_TYPE: INDUCTOR\POWER; ROHS: Yes; Tolerance: 20%
Q1 = MOSFET_P: TRAN PMOS PWR 4.1A 8V SOT23; AGILE_PN: 480-77918; CAD_APPROVED: Yes; HEIGHT: 1.12MM; MFG_NAME01: VISHAY INTERTECHNOLOGY; MFG_PN01: SI2305ADS-T1-GE3; ROHS: Yes
R5 = RES: RES MF 200K 1/16W 5% 0402; AGILE_PN: 470-30326; ASSY_OPT: DNP; CAD_APPROVED: Yes; FPLIST: RC0402_25,RC0402_HD,0402_CC; MFG_NAME01: YAGEO AMERICA; MFG_PN01: RC0402JR-07200KL; ROHS: Yes; Tolerance: 5%
R9 = RES: RES MF 10K 1/16W 5% 0402; AGILE_PN: 470-75557; CAD_APPROVED: Yes; FPLIST: RC0402_25,RC0402_HD,0402_CC; MFG_NAME01: VISHAY INTERTECHNOLOGY; MFG_PN01: CRCW040210K0JNED; ROHS: Yes; Tolerance: 5%
R10 = RES: RES MF 330 OHM 1/16W 5% 0402; AGILE_PN: 470-75613; CAD_APPROVED: Yes; FPLIST: RC0402_25,RC0402_HD,0402_CC; MFG_NAME01: VISHAY INTERTECHNOLOGY; MFG_PN01: CRCW0402330RJNED; ROHS: Yes; Tolerance: 5%
SW5 = SW_6P: SW DPDT SLD 30V 100MA TH; AGILE_PN: 510-76158; CAD_APPROVED: Yes; HEIGHT: 7.7MM; MFG_NAME01: TYCO ELECTRONICS; MFG_PN01: MMS22; ROHS: Yes
TL1-TL3 = TestLoop: TEST POINT PAD SIZE 3.4MM X 1.8MM SMT; AGILE_PN: 211-75906; CAD_APPROVED: Yes; FPLIST: testpoint_135_070mil,testpoint_110_045mil,testpoint_125x40milmod; HEIGHT: 1.53 MM; MFG_NAME01: KEYSTONE ELECTRONICS; MFG_PN01: 5015; ROHS: Yes
U1 = tps63001: IC LIN DCDC SYNC 3.3V OUTPUT 1250-1800KHZ 1.8-5.5V QFN-10; AGILE_PN: 315-77848; CAD_APPROVED: Yes; HEIGHT: 1MM; MFG_NAME01: TEXAS INSTRUMENTS; MFG_PN01: TPS63001DRCT; ROHS: Yes

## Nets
3V3_ELEV: J1.3(A2) J16.A3(3.3V_4) J16.A4(3.3V_5) J16.A36(3.3V_6) J16.A82(3.3V_7) J16.B3(3.3V_1) J16.B36(3.3V_2) J16.B82(3.3V_3) J16.C3(3.3V_11) J16.C4(3.3V_12) J16.C36(3.3V_13) J16.C82(3.3V_14) J16.D3(3.3V_8) J16.D36(3.3V_9) J16.D82(3.3V_10)
5V_ELEV: D12.C J1.5(A3) J9.1(A1) J16.A1(5V_2) J16.B1(5V_1) J16.C1(5V_4) J16.D1(5V_3)
GND: ANT1.2(GND) C1.2 C2.2 C3.2 C4.2 C7.2 C8.2 C9.2 C10.2 C11.2 C12.2 C13.2 C14.2 C15.2 C16.2 C19.2 C21.2 C22.2 C23.2 C24.2 C26.2 C27.2 C28.2 C29.2 C30.2 C31.2 C32.2 C33.2 C35.2 C36.2 C42.2 C43.2 C44.2 C45.2 C46.2 C47.2 C48.2 C49.2 C50.2 J4.2(SHIELD2) J4.3(SHIELD1) J4.4(SHIELD3) J4.5(SHIELD4) J5.2 J6.5(P5) J9.3(A2) J9.5(A3) J9.6(B3) J9.7(A4) J9.10(B5) J9.11(A6) J9.13(A7) J9.14(B7) J9.15(A8) J9.16(B8) J9.19(A10) J10.1(A1) J10.2(B1) J10.5(A3) J10.6(B3) J10.7(A4) J10.8(B4) J10.13(A7) J10.14(B7) J11.3(A2) J11.5(A3) J11.15(A8) J11.17(A9) J11.19(A10) J13.3(A2) J13.5(A3) J15.5(P5) J16.A2(GND_9) J16.A5(GND_10) J16.A6(GND_11) J16.A26(GND_12) J16.A31(GND_13) J16.A49(GND_14) J16.A65(GND_15) J16.A81(GND_16) J16.B2(GND_1) J16.B5(GND_2) J16.B6(GND_3) J16.B26(GND_4) J16.B31(GND_5) J16.B49(GND_6) J16.B65(GND_7) J16.B81(GND_8) J16.C2(GND_25) J16.C5(GND_26) J16.C6(GND_27) J16.C26(GND_28) J16.C31(GND_29) J16.C49(GND_30) J16.C65(GND_31) J16.C81(GND_32) J16.D2(GND_17) J16.D5(GND_18) J16.D6(GND_19) J16.D26(GND_20) J16.D31(GND_21) J16.D49(GND_22) J16.D65(GND_23) J16.D81(GND_24) J28.2 J30.1 L3.2 L5.2 L7.2 L8.2 Q2.2(EMITTER) R5.2 R9.2 R10.2 R95.1 R100.2 R109.2 R112.2 R562.2 SW1.1 SW1.2 SW2.1 SW2.2 SW3.1 SW3.2 SW4.1 SW4.2 SW6.3 SW6.4 TL1.1(Pin1) TL2.1(Pin1) TL3.1(Pin1) TP9.1(Pin1) TP10.1(Pin1) TP11.1(Pin1) TP12.1(Pin1) TP507.1(Pin1) U1.3(PGND) U1.9(GND) U1.11(PPAD) U3.28(VSSA) U3.48(GND_PA) U3.51(GND_PA) U3.63(NC) U3.64(EP_GND1) U3.65(EP_GND2) U4.7(GND) U6.2(VSS1) U6.8(VSSA) U6.33(EPAD) U7.2(GND) U8.3(COM_ANODE) U10.2(A2) U11.2(A2) U12.2(A2) U13.7(GND) U14.2(GND) Y1.2 Y1.4 Y3.2(GND1) Y3.4(GND2) Z1.5(CT)
P5V0_SDA_USB_CONN_VBUS: J15.1(P1) L6.1
P5V_K24_USB: J6.1(P1) L4.1 U10.1(A1)
P5V_KW24_USB: C50.1 D15.C J27.1
P5V_SDA: C33.1 C34.1 C49.1 D13.C R52.1 R108.1 TP104.1(Pin1) U6.6(VREGIN) U7.1(VIN)
P5V_USB: D12.A J1.1(A1) J12.2 U7.6(VOUT)
VCC: J2.1(A1) J2.3(A2) J2.5(A3) J3.2 TP5.1(Pin1)
VDD_IF: C42.1 C43.1 C44.1 U3.52(VDD_PA) U3.53(VDD_IF) U3.54(VDD_RF)
VDD_REGD: C15.1 C16.1 U3.43(VDD_REGD)
VDDA: J16.A46(VDDA)
VSSA: J16.A45(VSSA)
CLK_OUT: R83.1 TP27.1(Pin1) U3.39(PTA18/EXTAL0/FTM0_FLT2/FTM_CLKIN0)
ELE_PS_SENSE: J16.B4(ELE_PS_SENSE_1) J16.D4(ELE_PS_SENSE_2) R111.1
EXTAL_32: R82.2 R83.2 U3.31(EXTAL32)
EXTAL_32K: C23.1 R82.1 Y2.1
EXTAL_32M: C20.2 C21.1 U3.1(EXTAL_32M) Y1.1
EZP_CSR_B: J11.9(A5) R26.2 R27.2
GPIO1: J10.15(A8) J16.D50(GPIO23) U3.2(GPIO1)
GPIO2: J10.16(B8) J16.D51(GPIO24) U3.3(GPIO2)
GPT_VBRD: J8.2 J9.2(B1)
GPT_VDA: J9.4(B2) R20.1
K24_USB_SHLD: J6.S1(SHLD1) J6.S2(SHLD2) J6.S3(SHLD3) J6.S4(SHLD4) L8.1
KW24_USB_DN: J6.2(P2) R33.1 U11.1(A1)
KW24_USB_DP: J6.3(P3) R34.1 U12.1(A1)
POWER_EN: R551.1 U6.31(ADC0_SE7B/PTD6/SPI0_PCS3/UART0_RX/FTM0_CH6/FTM0_FLT0/LLWU_P15)
PTA0: J11.4(B2) R93.2 U3.33(PTA0/JTAG_TCLK/SWD_CLK/EZP_CLK/~{UART0_CTS}/~{UART0_COL}/FTM0_CH5)
PTA1: J11.8(B4) U3.34(PTA1/JTAG_TDI/EZP_DI/UART0_RX/FTM0_CH6)
PTA2: J11.6(B3) U3.35(PTA2/JTAG_TDO/TRACE_SWO/EZP_DO/UART0_TX/FTM0_CH7)
PTA3: J11.2(B1) R25.1 R92.2 U3.36(PTA3/JTAG_TMS/SWD_DIO/~{UART0_RTS}/FTM0_CH0)
PTA4: R27.1 U3.37(PTA4/LLWU_P3/~{NMI}/~{EZP_CS}/FTM0_CH1)
PTA19: R564.2 U3.40(PTA19/XTAL0/FTM1_FLT0/FTM_CLKIN1/LPTMR0_ALT1)
PTB10_TWRPI: J10.11(A6) J16.B9(SDHC_D3/~{SPI1_CS0}) J17.3(C1) R73.1 R553.2 TP506.1(Pin1) U13.4(~{CS})
PTB11_TWRPI: J10.12(B6) J16.B7(SDHC_CLK/SPI1_CLK) J17.6(C2) R72.1 R554.2 TP504.1(Pin1) U13.2(SCK)
PTB16_TWRPI: J10.10(B5) J16.B10(SDHC_CMD/SPI1_MOSI) J17.9(C3) R71.1 R555.2 TP500.1(Pin1) U13.1(SI)
PTB17_TWRPI: J10.9(A5) J16.B11(SDHC_D0/SPI1_MISO) J17.12(C4) R70.1 R552.2 TP501.1(Pin1) U13.8(SO)
PTC4: J17.2(B1) R66.2 R78.1 SW1.3 SW1.4
PTC4_A: J16.B46(~{SPI0_CS0}) J17.1(A1)
PTC5: J17.5(B2) R67.2 R79.1 SW2.3 SW2.4
PTC5_A: J16.B48(SPI0_CLK) J17.4(A2)
PTC6: J17.8(B3) R68.2 R80.1 SW3.3 SW3.4
PTC6_A: J16.B45(SPI0_MOSI/IO0) J17.7(A3)
PTC7: J17.11(B4) R69.2 R81.1 SW4.3 SW4.4
PTC7_A: J16.B44(SPI0_MISO/IO1) J17.10(A4)
PTD1: J9.9(A5) J16.B63(EBI_ALE/~{EBI_CS1}) U3.8(PTD1/ADC0_SE5B/SPI0_SCK/~{UART2_CTS})
PTD2: J10.3(A2) J16.A7(I2C0_SCL) J16.A53(GPIO17) J16.B52(GPIO5/SPI0_HOLD/IO3) R21.2 R74.1 R77.2 U3.9(PTD2/LLWU_P13/SPI0_SOUT/UART2_RX/I2C_SDA/GPIO4_BSM_DATA)
PTD3: J10.4(B2) J16.A8(I2C0_SDA) J16.A60(I2S0_DIN1) R22.2 R75.2 R76.2 U3.10(PTD3/SPI0_SIN/UART2_TX/I2C_SCL/GPIO5_BSM_CLK)
PTD4: J16.B47(~{SPI0_CS1}) J19.2 U3.11(PTD4/LLWU_P14/MADC0_SE21/SPI0_PCS1/~{UART0_RTS}/FTM0_CH4/EWM_IN/GPIO_BSM_FRAME)
PTD4_LED: J19.3 R16.2
PTD4_TWR: J16.A78(EBI_AD2) J19.1
PTD5: J20.2 U3.12(PTD5/ADC0_SE6B/SPI0_PCS2/~{UART0_CTS}/~{UART0_COL}/FTM0_CH5/~{EWM_OUT})
PTD5_LED: J20.3 R17.2
PTD5_TWR: J16.A79(EBI_AD1) J20.1
PTD6: J21.2 U3.13(PTD6/LLWU_P15/ADC0_SE7B/SPI0_PCS3/UART0_RX/FTM0_CH6/FTM0_FLT0)
PTD6_LED: J21.3 R18.2
PTD6_TWR: J16.A41(UART0_RX) J16.A80(EBI_AD0) J21.1 R64.1
PTD7: J24.2 U3.14(PTD7/MADC0_SE22/CMT_IRO/UART0_TX/FTM0_CH7/FTM0_FLT1)
PTD7_LED: J24.3 R19.2
PTD7_TWR: J16.A42(UART0_TX) J24.1
PTE0: J11.12(B6) J18.2(B1) R58.1 U3.15(PTE0/MADC0_SE10/SPI1_PCS1/UART1_TX/MTRACE_CLKOUT/I2C1_SDA/RTC_CLKOUT)
PTE0_TWR: J16.A44(UART1_TX) J18.1(A1) R65.1 R88.2
PTE0_TWRPI: J9.8(B4) J18.3(C1)
PTE1: J11.20(B10) J18.5(B2) U3.16(PTE1/LLWU_P0/MADC0_SE11/SPI1_SOUT/UART1_RX/MTRACE_D3/I2C1_SCL/SPI1_SIN)
PTE1_TWR: J16.A43(UART1_RX) J18.4(A2) R62.2 R89.2
PTE1_TWRPI: J9.12(B6) J18.6(C2) R60.1
PTE2: J11.18(B9) J18.8(B3) U3.17(PTE2/LLWU_P1/MADC0_DP1/SPI1_SCK/~{UART1_CTS}/MTRACE_D2)
PTE2_TWR: J16.A9(GPIO9/UART1_CTS) J18.7(A3) R59.2 R90.2
PTE2_TWRPI: J9.17(A9) J18.9(C3) R23.2
PTE3: J11.16(B8) J18.11(B4) U3.18(PTE3/MADC0_DM1/SPI1_SIN/~{UART1_RTS}/MTRACE_D1/SPI1_SOUT)
PTE3_TWR: J16.B21(GPIO1/UART1_RTS) J18.10(A4) R61.2 R91.2
PTE3_TWRPI: J9.18(B9) J18.12(C4) R24.2 R63.1
PTE4: J11.14(B7) R566.2 U3.19(PTE4/LLWU_P2/SPI1_PCS0/MTRACE_D0)
PTE16/UART2_TX: J10.18(B9) J16.C42(UART2_TXD/TSI1) R84.1
PTE16/UART2_TX/USB_DP: C48.1 R34.2 R84.2 U3.21(PTE16/ADC0_SE4A/SPI0_PCS0/UART2_TX/FTM_CLKIN0/FTM0_FLT3)
PTE17/UART2_RX: J10.17(A9) J16.C41(UART2_RXD/TSI0) R85.1
PTE17/UART2_RX/USB_DN: C35.1 R33.2 R85.2 U3.22(PTE17/ADC0_SE5A/SPI0_SCK/UART2_RX/FTM_CLKIN1/LPTMR0_ALT3)
PTE18/UART2_CTS: J10.19(A10) J16.C44(UART2_CTS/TSI3) R86.1
PTE18/UART2_CTS/VOUT33: C27.1 C28.1 D14.A R86.2 U3.23(PTE18/ADC0_SE6A/SPI0_SOUT/~{UART2_CTS}/I2C0_SDA)
PTE19/UART2_RTS: J10.20(B10) J16.C43(UART2_RTS/TSI2) R87.1
PTE19/UART2_RTS/VREGIN: J27.2 R87.2 U3.24(PTE19/ADC0_SE7A/SPI0_SIN/~{UART2_RTS}/I2C0_SCL)
RESET_B: R94.2 U14.3(A)
RF_50: C17.1 C18.2 C19.1 L5.1 Z1.1(UNBAL1)
RF_ANT: ANT1.1(Signal) C18.1
RST_TGTMCU_B: C29.1 D9.C(CATHODE) J9.20(B10) J11.10(B5) J29.1 R560.2 R561.2 SW6.1 SW6.2 U3.41(~{RESET})
RSTR: D9.A(ANODE) R46.2
SDA_EXTAL: C31.1 U6.17(EXTAL0/PTA18/FTM0_FLT2/FTM_CLKIN0) Y3.3
SDA_JTAG_TCLK: J13.4(B2) TP509.1(Pin1) U6.12(JTAG_TCLK/SWD_CLK/EZP_CLK/TSI0_CH1/PTA0/~{UART0_CTS}/~{UART0_COL}/FTM0_CH5)
SDA_JTAG_TDI: J13.8(B4) TP511.1(Pin1) U6.13(JTAG_TDI/EZP_DI/TSI0_CH2/PTA1/UART0_RX/FTM0_CH6)
SDA_JTAG_TDO: J13.6(B3) TP510.1(Pin1) U6.14(JTAG_TDO/TRACE_SWO/EZP_DO/TSI0_CH3/PTA2/UART0_TX/FTM0_CH7)
SDA_JTAG_TMS: J13.2(B1) R107.2 TP508.1(Pin1) U6.15(JTAG_TMS/SWD_DIO/TSI0_CH4/PTA3/~{UART0_RTS}/FTM0_CH0)
SDA_LED: D11.C(CATHODE) TP106.1(Pin1) U6.29(PTD4/SPI0_PCS1/~{UART0_RTS}/FTM0_CH4/EWM_IN/LLWU_P14)
SDA_LED_R: D11.A(ANODE) R104.2
SDA_RST: J13.10(B5) R52.2 R100.1 TP105.1(Pin1) TP512.1(Pin1) U6.19(~{RESET})
SDA_SPI0_SCK: U4.12(4A) U6.26(PTC5/SPI0_SCK/LPTMR0_ALT2/I2S0_RXD0/CMP0_OUT/LLWU_P9)
SDA_SPI0_SIN: R112.1 U4.8(3Y) U6.28(CMP0_IN1/PTC7/SPI0_SIN/USB_SOF_OUT/I2S0_RX_FS)
SDA_SPI0_SOUT: U4.2(1A) U6.27(CMP0_IN0/PTC6/SPI0_SOUT/PDB0_EXTRG/I2S0_RX_BCLK/I2S0_MCLK/LLWU_P10)
SDA_SWD_EN: R106.2 U4.10(~{OE3}) U4.13(~{OE4}) U6.16(~{NMI}/~{EZP_CS}/TSI0_CH5/PTA4/FTM0_CH1/LLWU_P3)
SDA_SWD_OE_B: R105.1 U4.1(~{OE1}) U6.20(ADC0_SE8/TSI0_CH0/PTB0/I2C0_SCL/FTM1_CH0/FTM1_QD_PHA/LLWU_P5)
SDA_USB_CONN_DN: J15.2(P2) R50.1 U8.1(CATHODE1)
SDA_USB_CONN_DP: J15.3(P3) R51.1 U8.2(CATHODE2)
SDA_USB_DN: R50.2 U6.4(USB0_DM)
SDA_USB_DP: R51.2 U6.3(USB0_DP)
SDA_USB_VOUT33: C26.1 C32.1 D16.A(ANODE) J13.1(A1) R104.1 R105.2 R106.1 R107.1 R110.1 TP103.1(Pin1) U4.4(~{OE2}) U4.14(VCC) U6.1(VDD1) U6.5(VOUT33) U6.7(VDDA) U6.11(VBAT)
SDA_USBSHIELD: J15.S1(SHLD1) J15.S2(SHLD2) J15.S3(SHLD3) J15.S4(SHLD4) L7.1
SDA_XTAL: C30.1 U6.18(XTAL0/PTA19/FTM1_FLT0/FTM_CLKIN1/LPTMR0_ALT1) Y3.1
SWD_CLK_TGTMCU: R93.1 U4.11(4Y)
SWD_DIO_TGTMCU: R92.1 U4.3(1Y) U4.9(3A)
TC_74125_SPARE_I_TP: R95.2 TP107.1(Pin1) U4.5(2A)
TC_74125_SPARE_O_TP: TP108.1(Pin1) U4.6(2Y)
TC_EXTAL_TP: TP102.1(Pin1) U6.10(EXTAL32)
TC_SDA_USB_ID_TP: J15.4(P4) TP100.1(Pin1)
TC_XTAL_TP: TP101.1(Pin1) U6.9(XTAL32)
TGT_PWR: J11.11(A6) J11.13(A7) J12.1
UART1_CTS_TGTMCU: R90.1 U6.22(ADC0_SE15/TSI0_CH14/PTC1/SPI0_PCS3/~{UART1_RTS}/FTM0_CH0/I2S0_TXD0/LLWU_P6)
UART1_RST_TGTMCU: R91.1 U6.23(ADC0_SE4B/CMP1_IN0/TSI0_CH15/PTC2/SPI0_PCS2/~{UART1_CTS}/FTM0_CH1/I2S0_TX_FS)
UART1_RX_TGTMCU: R89.1 U6.25(PTC4/SPI0_PCS0/UART1_TX/FTM0_CH3/CMP1_OUT/LLWU_P8)
UART1_TX_TGTMCU: R88.1 U6.24(CMP1_IN1/PTC3/SPI0_PCS1/UART1_RX/FTM0_CH2/I2S0_TX_BCLK/LLWU_P7)
V_EXT: J28.1 Q1.2(SOURCE)
V_LED: D4.A(ANODE) D5.A(ANODE) D6.A(ANODE) D7.A(ANODE) D8.A(ANODE) R4.2 R46.1 TP4.1(Pin1)
V_MAIN: D1.C D3.C SW5.1 TP1.1(Pin1)
V_MCU: C7.1 C8.1 C9.1 C13.1 C14.1 C46.1 C47.1 J8.1 J11.1(A1) L2.2 R6.2 R12.1 R20.2 R21.1 R22.1 R23.1 R24.1 R25.2 R26.1 R552.1 R553.1 R554.1 R555.1 R560.1 R563.2 R565.2 TP6.1(Pin1) TP502.1(Pin1) U3.20(VDD_MCU) U3.25(VDDA) U3.32(VBAT_MCU) U3.38(VDD_MCU) U13.6(VCC) U14.6(VCCB)
V_REG: C2.1 C3.1 D2.A R2.1 TP3.1(Pin1) U1.1(VOUT)
V_RF: C10.1 C11.1 C12.1 R8.2 TP7.1(Pin1) U3.42(VBAT2_RF) U3.55(VBAT_RF)
VOUT33: J3.3 SW5.5
VOUT33_SW: D14.C SW5.6
VREG_IN: C1.1 R1.1 SW5.2 TP2.1(Pin1) U1.5(VIN)
VTRG_EN: Q2.3(COLLECTOR) R108.2 R109.1 R551.2 U7.3(ENABLE)
VTRG_FAULT_B: R110.2 U6.32(PTD7/CMT_IRO/UART0_TX/FTM0_CH7/FTM0_FLT1) U7.4(~{FAULT})
XTAL_32: C24.1 U3.30(XTAL32) Y2.2
XTAL_32M: R15.1 U3.56(XTAL_32M)
XTAL_32M_R: C22.1 R15.2 Y1.3
Z_RF_N: C25.2 R14.2 Z1.3(BAL3)
Z_RF_P: C25.1 R13.2 Z1.4(BAL4)
N23265787: D4.C(CATHODE) R10.1
N23279171: D5.C(CATHODE) R16.1 TP14.1(Pin1)
N23279177: D6.C(CATHODE) R17.1 TP15.1(Pin1)
N23279197: D8.C(CATHODE) R19.1 TP17.1(Pin1)
N23279203: D7.C(CATHODE) R18.1 TP16.1(Pin1)
N23310364: R78.2 U3.4(PTC4/LLWU_P8/SPI0_PCS0/UART1_TX/FTM0_CH3/CMP1_OUT)
N23310371: R79.2 U3.5(PTC5/LLWU_P9/SPI0_SCK/LPTMR0_ALT2/I2S0_RXD0/CMP0_OUT)
N23310378: R80.2 U3.6(PTC6/LLWU_P10/CMP0_IN0/SPI0_SOUT/PDB0_EXTRG/I2S0_RX_BCLK/I2S0_MCLK)
N23310385: R81.2 U3.7(PTC7/CMP0_IN1/SPI0_SIN/USB_SOF_OUT/I2S0_RX_FS)
N23310563: J16.A37(PWM3) J16.A69(EBI_AD11) R66.1
N23310622: J16.A24(I2S0_DIN0) J16.A70(EBI_AD10) R67.1
N23310905: J16.A58(I2S0_DIN_SCK) J16.A71(EBI_AD9) R68.1
N23310921: J16.A59(I2S0_DIN_WS) J16.A72(EBI_AD8) R69.1
N23313140: J16.A76(EBI_AD4) R77.1
N23313187: J16.A77(EBI_AD3) R75.1
N23313323: J16.B38(PWM6) R64.2
N23325134: J16.B23(GPIO3) J16.B25(CLKOUT1) R65.2
N23327200: R12.2 U3.29(TAMPER0/~{RTC_WAKEUP})
N23340195: L3.1 U3.27(VREFL)
N23345722: R14.1 U3.50(RF_OUTN)
N23346446: R13.1 U3.49(RF_OUTP)
N23353475: C20.1 J5.1
N23360966: C36.1 L2.1 U3.26(VREFH)
N23363687: J16.B27(AN7) R58.2
N23363690: J16.B28(AN6) R60.2
N23363940: J16.A27(AN3) R59.1
N23363943: J16.A28(AN2) R61.1
N23364230: J16.A29(AN1) R62.1
N23364481: J16.B71(EBI_R/~{W}) R74.2
N23364514: J16.B67(EBI_AD16) R70.2
N23364562: J16.B68(EBI_AD17) R71.2
N23364605: J16.B70(EBI_AD19) R73.2
N23364648: J16.B69(EBI_AD18) R72.2
N23364699: J16.B30(AN4) R63.2
N23366702: TP26.1(Pin1) U3.46(RX_SWITCH)
N23421288: J16.A75(EBI_AD5) R76.1
N23440330: TP21.1(Pin1) U3.44(ANT_A)
N23440333: TP22.1(Pin1) U3.45(ANT_B)
N23460837: C45.1 Z1.2(UNBAL2)
N23503244: C17.2 J4.1(CENTER)
N23570419: D15.A L4.2
N23642836: C4.1 R1.2 U1.6(EN) U1.7(PS/SYNC) U1.8(VINA)
N23642972: L1.2 U1.2(L2)
N23642976: L1.1 U1.4(L1)
N23643006: R2.2 R5.1 U1.10(FB)
N23643076: Q1.1(GATE) R7.2 R9.1
N23643080: D3.A Q1.3(DRAIN)
N23643183: D2.C J3.1
N23643259: J2.2(B1) R4.1
N23643265: J2.4(B2) R6.1
N23643271: J2.6(B3) R8.1
N23643416: D1.A J1.2(B1) J1.4(B2) J1.6(B3) R7.1
N23645388: R563.1 R564.1 U13.3(~{RESET})
N23645400: R565.1 R566.1 U13.5(~{WP})
N23647269: D16.C(CATHODE) R562.1 U14.1(VCCA) U14.5(OE)
N23647277: J30.2 R94.1 U6.21(ADC0_SE9/TSI0_CH6/PTB1/I2C0_SDA/FTM1_CH1/FTM1_QD_PHB)
N23648037: C34.2 U7.5(CSLEW)
N23648090: Q2.1(BASE) R111.2
N23648321: D13.A L6.2
N23648566: J29.2 U14.4(B)
N23649169: J16.A63(~{RSTOUT}) R561.1
N23664400: TP25.1(Pin1) U3.47(TX_SWITCH)

Not connected (* = marked no-connect by the designer): J6 4(P4); J13 7(A4)* 9(A5)*; J16 A10(GPIO8/SDHC_D2)* A11(GPIO7/SD_WP_DET)* A12(ETH_CRS)* A13(ETH_MDC_1)* A14(ETH_MDIO_1)* A15(ETH_RXCLK_1)* A16(ETH_RXDV_1)* A17(ETH_RXD3)* A18(ETH_RXD2)* A19(ETH_RXD1_1)* A20(ETH_RXD0_1) A21(I2S0_MCLK)* A22(I2S0_DOUT_SCK)* A23(I2S0_DOUT_WS)* A25(I2S0_DOUT0)* A30(AN0)* A32(DAC0)* A33(TMR1) A34(TMR0) A35(GPIO6)* A38(PWM2)* A39(PWM1)* A40(PWM0)* A47(CAN1_RX)* A48(CAN1_TX)* A50(GPIO14) A51(GPIO15) A52(GPIO16/SPI0_WP/IO2) A54(USB0_DM) A55(USB0_DP) A56(USB0_ID)* A57(USB0_VBUS) A61(I2S0_DOUT1) A62(~{RSTIN}) A64(CLKOUT0) A66(EBI_AD14)* A67(EBI_AD13)* A68(EBI_AD12)* A73(EBI_AD7)* A74(EBI_AD6)* B8(SDHC_D3/~{SPI1_CS1}) B12(ETH_COL_1)* B13(ETH_RXER_1)* B14(ETH_TXCLK_1)* B15(ETH_TXEN_1)* B16(ETH_TXER)* B17(ETH_TXD3)* B18(ETH_TXD2)* B19(ETH_TXD1_1)* B20(ETH_TXD0_1)* B22(GPIO2/SDHC_D1)* B24(CLKIN0) B29(AN5)* B32(DAC1)* B33(TMR3)* B34(TMR2)* B35(GPIO4)* B37(PWM7)* B39(PWM5)* B40(PWM4)* B41(CAN0_RX)* B42(CAN0_TX)* B43(1WIRE)* B50(I2C1_SCL) B51(I2C1_SDA) B53(RSRV)* B54(RSRV)* B55(IRQ_H)* B56(IRQ_G)* B57(IRQ_F)* B58(IRQ_E)* B59(IRQ_D)* B60(IRQ_C)* B61(IRQ_B)* B62(IRQ_A)* B64(~{EBI_CS0})* B66(EBI_AD15)* B72(~{EBI_OE})* B73(EBI_D7)* B74(EBI_D6)* B75(EBI_D5)* B76(EBI_D4)* B77(EBI_D3)* B78(EBI_D2)* B79(EBI_D1)* B80(EBI_D0)* C7(I2C2_SCL)* C8(I2C2_SDA)* C9(GPIO25) C10(ULPI_STOP)* C11(ULPI_CLK)* C12(GPIO26) C13(ETH_MDC_2)* C14(ETH_MDIO_2)* C15(ETH_RXCLK_2)* C16(ETH_RXDV_2)* C17(GPIO27/SDHC_D6)* C18(GPIO28/SDHC_D7)* C19(ETH_RXD1_2)* C20(ETH_RXD0_2)* C21(ULPI_DATA0/I2S1_MCLK)* C22(ULPI_DATA1/I2S1_DOUT_SCK)* C23(ULPI_DATA2/I2S1_DOUT_WS)* C24(ULPI_DATA3/I2S1_DIN0)* C25(ULPI_DATA4/I2S1_DOUT0)* C27(AN11)* C28(AN10)* C29(AN9)* C30(AN8)* C32(GPIO29/UART2_DCD) C33(TMR9)* C34(TMR8)* C35(GPIO30/UART3_DCD) C37(PWM11)* C38(PWM10)* C39(PWM9)* C40(PWM8)* C45(UART3_RXD/TSI4)* C46(UART3_TXD/TSI5)* C47(UART3_RTS/CAN3_RX)* C48(UART3_CTS/CAN3_TX)* C50(LCD_D4/LCD_P4)* C51(LCD_D5/LCD_P5)* C52(LCD_D6/LCD_P6)* C53(LCD_D7/LCD_P7)* C54(LCD_D8/LCD_P8)* C55(LCD_D9/LCD_P9)* C56(LCD_D10/LCD_P10)* C57(LCD_D11/LCD_P11)* C58(I2S1_DIN_SCK)* C59(I2S1_DIN_WS)* C60(I2S1_DIN1)* C61(I2S1_DOUT1)* C62(LCD_D15/LCD_P15)* C63(LCD_D16/LCD_P16/SD_GND)* C64(LCD_D17/LCD_P17/SD_GND)* C66(~{EBI_BE_32_24}/LCD_P28/SD_TX_0+)* C67(~{EBI_BE_23_16}/LCD_P29/SD_TX_0-)* C68(~{EBI_BE_15_8}/LCD_P30/SD_GND)* C69(~{EBI_BE_7_0}/LCD_P31/SD_GND)* C70(EBI_TSIZE0/LCD_P32/SD_TX_1+)* C71(EBI_TSIZE1/LCD_P33/SD_TX_1-)* C72(~{EBI_TS}/LCD_P34/SD_GND)* C73(~{EBI_TBST}/LCD_P35/SD_GND)* C74(~{EBI_TA}/LCD_P36/SD_TX_2+)* C75(~{EBI_CS4}/LCD_P37/SD_TX_2-)* C76(~{EBI_CS3}/LCD_P38/SD_GND)* C77(~{EBI_CS2}/LCD_P39/SD_GND)* C78(~{EBI_CS1}/LCD_P40/SD_TX_3+)* C79(GPIO31/LCD_P41/SD_TX_3-)* C80(LCD_D23/LCD_P23/SD_GND)* D7(SPI2_CLK)* D8(~{SPI2_CS1})* D9(~{SPI2_CS0})* D10(SPI2_MOSI)* D11(SPI2_MISO)* D12(ETH_COL_2)* D13(ETH_RXER_2)* D14(ETH_TXCLK_2)* D15(ETH_TXEN_2)* D16(GPIO18)* D17(GPIO19/SDHC_D4)* D18(GPIO20/SDHC_D5)* D19(ETH_TXD1_2)* D20(ETH_TXD0_2)* D21(ULPI_NEXT/USB_HS_DM)* D22(ULPI_DIR/USB_HS_DP)* D23(UPLI_DATA5/USB_HS_VBUS)* D24(ULPI_DATA6/USB_HS_ID)* D25(ULPI_DATA7)* D27(LCD_HSYNC/LCD_P24)* D28(LCD_VSYNC/LCD_P25)* D29(AN13)* D30(AN12)* D32(LCD_CLK/LCD_P26)* D33(TMR11)* D34(TMR10)* D35(GPIO21) D37(PWM15)* D38(PWM14)* D39(PWM13)* D40(PWM12)* D41(CAN2_RX)* D42(CAN2_TX)* D43(LCD_CONTRAST)* D44(LCD_OE/LCD_P27)* D45(LCD_D0/LCD_P0)* D46(LCD_D1/LCD_P1)* D47(LCD_D2/LCD_P2)* D48(LCD_D3/LCD_P3)* D52(LCD_D12/LCD_P12)* D53(LCD_D13/LCD_P13)* D54(LCD_D14/LCD_P14)* D55(IRQ_P/~{SPI2_CS2})* D56(IRQ_O/~{SPI2_CS3})* D57(IRQ_N)* D58(IRQ_M)* D59(IRQ_L)* D60(IRQ_K)* D61(IRQ_J)* D62(IRQ_I)* D63(LCD_D18/LCD_P18/SD_RX_0+)* D64(LCD_D19/LCD_P19/SD_RX_0-)* D66(EBI_AD20/LCD_P42/SD_GND)* D67(EBI_AD21/LCD_P43/SD_GND)* D68(EBI_AD22/LCD_P44/SD_RX_1+)* D69(EBI_AD23/LCD_P45/SD_RX_1-)* D70(EBI_AD24/LCD_P46/SD_GND)* D71(EBI_AD25/LCD_P47/SD_GND)* D72(EBI_AD26/LCD_P48/SD_RX_2+)* D73(EBI_AD27/LCD_P49/SD_RX_2-)* D74(EBI_AD28/LCD_P50/SD_GND)* D75(EBI_AD29/LCD_P51/SD_GND)* D76(EBI_AD30/LCD_P52/SD_RX_3+)* D77(EBI_AD31/LCD_P53/SD_RX_3-)* D78(LCD_D20/LCD_P20/SD_GND)* D79(LCD_D21/LCD_P21/SD_REFCLK+)* D80(LCD_D22/LCD_P22/SD_REFCLK-)*; SW5 3* 4*; U3 57(NC)* 58(NC)* 59(NC)* 60(NC)* 61(NC)* 62(NC)*; U6 30(ADC0_SE6B/PTD5/SPI0_PCS2/~{UART0_CTS}/~{UART0_COL}/FTM0_CH5/~{EWM_OUT})*; Z1 6(NC)*

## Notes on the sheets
sheet 1
- Table of Contents
- Revisions
- 2
- NOTES
- Rev
- Description
- Date
- Approved
- 3
- Block Diagram
- A
- Initial Release
- A. QUIROZ
- 02/11/2013
- 4
- POWER SUPPLY
- B
- Flash Memory/ Reset /
  Remove Battery
- 05/24/2013
- A. QUIROZ
- 5
- MOHAVE
- 6
- PERIPHERALS
- C
- PWR USB MODE   U14
  TXB01 for TXS01
- 08/11/2013
- A. QUIROZ
- 7
- OpenSDA
- 8
- TOWER CONNECTORS
- TWR-KW21D256
- • KW21D256 (no USB)
- SCH-27846
sheet 2
- 1. Unless Otherwise Specified:
- All resistors are in ohms, 5%, 1/8 Watt
- All capacitors are in uF, 20%, 50V
- All voltages are DC
- All polarized capacitors are aluminum electrolytic
- 2. Interrupted lines coded with the same letter or letter
      combinations are electrically connected.
- 3. Device type number is for reference only. The number
      varies with the manufacturer.
- 4. Special signal usage:
- _B Denotes - Active-Low Signal
- <> or [] Denotes - Vectored Signals
- 5. Interpret diagram in accordance with American
  National Standards Institute specifications, current
  revision, with the exception of logic block symbology.
- NOTE A.  R84, R85, R86 & R87 remove ONLY on
  USB IC (U3) version
- NOTE B.    C27 & C28 are DNP ONLY on
  NON-USB IC (U3) version
- NOTE C.    can use J3 2-3 to supply voltage
   only on USB IC (U3) version
- SCH-27846
sheet 3
- SCH-27846
sheet 4
- POWER ON
- SEE NOTE C
- 3.3V BUCK/BOOST REGULATOR
  TO USE TPS63000,
  REPLACE RESISTORS WITH
  THE FOLLOWING VALUES:
  R1 = 100 OHM, R2 = 1.24M
  AND POPULATE R5.
  OUTPUT VOLTAGE WILL BE 3.6V
- POWER SELECTOR
- LED VOLTAGE
- MCU VOLTAGE
- RF VOLTAGE
- External Voltage
- Power Switch
- SCH-27846
sheet 5
- HARMONIC TRAP
- USB / Non-USB SELECTOR
- USB HOST
- SEE NOTE A
- 32MHz XTAL
- XTAL_32M
- 32kHz XTAL
- XTAL_32K
- SEE NOTE B
- MKW24 (USB)
- SCH-27846
sheet 6
- SPI FLASH
- LEDS
- SWITCHING GPIO
- GENERAL PURPOSE
- TWRPI
- Default: 1-2
  (Remove to measure
  TWRPI current)
- NET NAMES
- PIN FUNCTIONS USED
- NET NAMES
- PIN FUNCTIONS USED
- SPI0 TWRPI/TWR_ELEV Select
- UART1/ADC TWRPI/TWR_ELEV_Select
- UART0/LED Select
- NET NAMES
- PIN FUNCTIONS USED
- NET NAMES
- PIN FUNCTIONS USED
- SCH-27846
sheet 7
- PIN FUNCTIONS USED
- NET NAMES
- KEY - PIN 7
- Default: no shunt
  (Disconnect Target Power)
- JTAG / SWD CONNECTOR
- MANUAL
  RESET
- DEBUGGER
- TARGET MCU
  INTERFACE
  SIGNALS
- TX
- RX
- CTS
- RTS
- PU/PD LOGIC:
  SERIAL INTERFACE
  IS ALWAYS RESET
  WHEN USB PORT
  IS DISCONNECTED
- OpenSDA INTERFACE
- SPARE 74HC125 buffer
- OpenSDA INTERFACE JTAG CONNECTOR
- SCH-27846
sheet 8
- SCH-27846
